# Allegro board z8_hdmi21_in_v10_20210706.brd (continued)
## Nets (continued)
GND: C1.2 C2.2 C3.2 C4.1 C5.2 C6.2 C7.2 C8.1 C9.2 C10.2 C11.2 C12.2 C13.1 C14.2 C15.2 C16.2 C17.2 C18.2 C19.2 C20.2 C21.2 C22.2 C23.2 C24.2 C25.2 C26.2 C27.2 C28.1 C29.2 C30.2 C31.2 C32.2 C33.2 C34.2 C36.2 C37.2 C38.2 C39.2 C40.2 C41.2 C42.2 C43.2 C44.1 C45.1 C46.1 C49.1 C50.2 C51.2 C52.2 C53.2 C54.2 C55.2 C56.2 C57.2 C58.2 C59.1 C60.2 C61.2 C62.2 C63.2 C64.2 C65.2 C66.2 C67.2 C68.2 C69.2 C70.2 C71.2 C72.2 C73.2 C75.2 C76.2 C77.2 C78.2 C79.2 C80.2 C81.2 C82.2 C83.2 C84.2 C85.2 C86.2 C87.2 C88.2 C89.2 C90.2 C91.2 C92.2 C93.2 C94.2 C95.2 C96.2 C97.2 C98.2 C99.2 C100.2 C101.2 C102.2 C103.2 C104.2 C105.2 C106.2 C107.2 C108.2 C109.2 C110.2 C111.1 C114.2 C118.2 C123.2 C124.2 C125.2 C126.2 C127.2 C128.2 C129.2 C131.2 C134.2 C135.2 C136.2 C137.2 C138.2 C139.2 C140.2 C141.2 C142.2 C143.2 C144.1 C145.2 C146.1 C147.2 C148.2 C149.2 C150.2 C151.2 C152.2 C153.2 C154.2 C155.2 C156.2 C157.2 C158.2 C159.2 C162.2 C163.2 C165.2 C166.2 C167.2 C168.2 C169.2 C170.2 C171.2 C173.2 C175.2 C176.2 C177.2 C179.2 C180.2 C182.1 C183.2 C188.2 C189.1 C192.2 C193.2 C195.2 C196.1 C197.2 C198.2 C200.2 C201.2 C203.2 C204.2 C205.2 C206.2 C207.2 C208.2 C209.2 C210.2 C211.2 C212.2 C213.2 C214.2 C215.2 C216.2 C217.2 C218.2 C219.2 C220.2 C221.2 C222.1 C223.2 C224.2 C225.2 C226.1 C227.2 C228.1 C229.2 C230.2 C231.2 C232.2 C233.2 C234.2 C235.2 C236.2 C237.2 C238.2 C239.2 C240.2 C241.2 C242.2 C243.2 C244.2 C248.2 C249.2 C253.2 C255.2 C256.2 C258.2 C265.2 C267.2 C268.2 C270.1 C271.1 C272.2 C273.2 C274.2 C275.2 C276.2 C277.2 C278.2 C279.2 C280.2 C281.1 C282.1 C283.2 C284.1 C285.1 C286.2 C287.2 C288.2 C289.2 C290.2 C291.2 C292.2 C293.2 C294.2 C297.2 C298.2 C299.2 C303.2 C304.2 C305.2 C306.2 C307.2 C308.2 C309.2 C310.2 C311.2 C312.2 C313.2 C314.2 C315.2 C316.2 C317.2 C318.2 C319.2 C320.2 C321.2 C322.2 C323.2 C324.2 C325.2 C326.2 C327.2 C328.2 C329.2 C330.2 C335.2 C337.2 C338.2 C339.2 C340.2 C341.2 C342.2 C343.2 C344.2 C345.2 C346.2 C347.2 C348.2 C349.2 C350.2 C351.2 C352.2 C353.2 C354.2 C355.2 C356.2 C357.2 C358.2 C359.2 C360.2 C361.2 C362.2 C363.2 C364.1 C365.2 C366.2 C367.2 C368.2 C369.2 C370.2 C371.2 C373.2 C374.2 C376.2 C377.2 C379.2 C380.2 C386.2 C387.2 C388.2 C389.2 C394.2 C395.2 C396.2 C397.2 C402.1 C403.1 C404.1 C405.1 C406.1 C407.1 C408.1 C409.1 C410.2 C411.1 C412.1 C413.1 C414.1 C415.1 C417.2 C421.2 C423.2 C425.2 C427.2 C429.2 C430.2 C432.2 C433.2 C434.2 C436.2 C437.2 C438.2 C439.2 C440.2 C441.2 C442.2 C443.2 C444.2 C445.2 C446.2 C447.2 C448.2 C449.2 C450.2 C451.2 C452.2 C453.2 C454.2 C455.2 C456.2 C457.2 C458.2 C459.2 C460.2 C461.2 C462.2 C463.2 C464.2 C465.2 C466.2 C467.2 C468.2 C469.2 C470.2 C471.2 C472.2 C473.2 C474.2 C475.2 C476.2 C477.2 C478.2 C479.2 C480.2 C481.2 C482.2 C483.2 C484.2 C485.2 C486.2 C487.2 C488.2 C489.2 C490.2 C491.2 C492.2 C493.2 C494.2 C495.2 C496.2 C497.2 C498.2 C499.2 C500.2 C501.2 C502.2 C503.2 C504.2 C505.2 C506.2 C507.2 C508.2 C509.2 C510.1 C511.1 C512.2 C513.2 C514.2 C515.2 C516.2 C517.2 C518.2 C519.2 C520.2 C521.2 C522.2 C523.2 C524.2 C525.2 C526.2 C527.2 C528.2 C529.2 C530.2 C531.2 C532.2 C533.2 C534.2 C535.2 C536.1 C537.1 C538.1 C539.1 C540.1 C541.1 C542.2 C543.2 C544.2 C545.2 C546.2 C547.2 C548.2 C549.2 C550.2 C551.2 C552.2 C553.2 C554.2 C555.2 C556.2 C557.2 C558.2 C559.2 C560.2 C561.2 C562.2 C563.2 C564.2 C565.2 C566.2 C567.2 C568.2 C569.2 C570.2 C571.2 C572.2 C573.2 C574.2 C575.2 C576.2 C577.2 C578.2 C579.2 C580.2 C581.2 C582.2 C583.2 C584.2 C585.2 C586.1 C587.1 C588.1 C589.1 C590.1 C591.2 C592.2 C593.2 C594.2 C595.2 C596.1 C597.1 C598.1 C599.1 C600.1 C601.1 C602.1 C603.1 C604.1 C605.1 C606.1 C607.1 C608.1 C609.2 C610.2 C611.2 C612.2 C613.2 C614.1 C615.1 C616.1 C617.1 C618.1 C619.1 C620.1 C621.1 C623.2 C624.2 C625.2 C627.1 C628.1 C629.1 C630.1 C631.1 C632.2 C700.2 C701.2 C702.2 C703.2 C704.1 FAN1.2 FAN2.2 HDMI1.2(DAT2_S) HDMI1.5(DAT1_S) HDMI1.8(DAT0_S) HDMI1.11(CLK_S) HDMI1.17(DDC/CEC GND) J4.2(6) J4.10 J6.2(DAT2_S) J6.5(DAT1_S) J6.8(DAT0_S) J6.11(CLK_S) J6.17(DDC/CEC GND) J8.2(DAT2_S) J8.5(DAT1_S) J8.8(DAT0_S) J8.11(CLK_S) J8.17(DDC/CEC GND) J10.2(DAT2_S) J10.5(DAT1_S) J10.8(DAT0_S) J10.11(CLK_S) J10.17(DDC/CEC GND) J11.6 J13.1 J13.2 J14.2(DAT2_S) J14.5(DAT1_S) J14.8(DAT0_S) J14.11(CLK_S) J14.17(DDC/CEC GND) J15.2 J15.3 JA1.3 JA1.4 JT1.AB1(G-CD1) JT1.AB2(G-CD2) JT1.AB3(G-CD3) JT1.AB4(G-CD4) JT1.AB5(G-CD5) JT1.AB6(G-CD6) JT1.AB7(G-CD7) JT1.AB8(G-CD8) JT1.AB9(G-CD9) JT1.AB10(G-CD10) JT1.CD1(G-CD5) JT1.CD2(G-CD4) JT1.CD3(G-CD3) JT1.CD4(G-CD2) JT1.CD5(G-CD1) JT1.CD6(G-CD6) JT1.CD7(G-CD7) JT1.CD8(G-CD8) JT1.CD9(G-CD9) JT1.CD10(G-CD10) L20.2 P1.A7(GND_A7) P1.A12(GND_A12) P1.A17(GND_A17) P1.A22(GND_A22) P1.A27(GND_A27) P1.A28(GND_A28) P1.A30(GND_A30) P1.A31(GND_A31) P1.A32(GND_A32) P1.A33(GND_A33) P1.AA2(GND_AA2) P1.AA12(GND_AA12) P1.AA17(GND_AA17) P1.AA22(GND_AA22) P1.AA25(GND_AA25) P1.AA26(GND_AA26) P1.AA29(GXBL1D_RX_CH2N,GXBL1D_REFCLK2N_) P1.AA30(GXBL1D_RX_CH2P,GXBL1D_REFCLK2P_) P1.AA31(GND_AA31) P1.AA32(GND_AA32) P1.AB4(GND_AB4) P1.AB19(GND_AB19) P1.AB26(GND_AB26) P1.AB29(GND_AB29) P1.AB30(GND_AB30) P1.AB31(GXBL1D_RX_CH1N,GXBL1D_REFCLK1N_) P1.AB32(GXBL1D_RX_CH1P,GXBL1D_REFCLK1P_) P1.AB33(GND_AB33) P1.AB34(GND_AB34) P1.AC1(GND_AC1) P1.AC11(GND_AC11) P1.AC16(GND_AC16) P1.AC17(IO_2A_0_AC17/DEV_CLRN/LVDS2A_24) P1.AC19(VREFB2AN0_2A_AC19) P1.AC25(GND_AC25) P1.AC29(GXBL1D_RX_CH0N,GXBL1D_REFCLK0N_) P1.AC30(GXBL1D_RX_CH0P,GXBL1D_REFCLK0P_) P1.AC31(GND_AC31) P1.AC32(GND_AC32) P1.AD3(GND_AD3) P1.AD13(GND_AD13) P1.AD18(GND_AD18) P1.AD21(GND_AD21) P1.AD23(GND_AD23) P1.AD26(GND_AD26) P1.AD29(GND_AD29) P1.AD30(GND_AD30) P1.AD31(GXBL1C_RX_CH5N,GXBL1C_REFCLK5N_) P1.AD32(GXBL1C_RX_CH5P,GXBL1C_REFCLK5P_) P1.AD33(GND_AD33) P1.AD34(GND_AD34) P1.AE5(GND_AE5) P1.AE13(GND_AE13) P1.AE15(GND_AE15) P1.AE26(GND_AE26) P1.AE29(GXBL1C_RX_CH4N,GXBL1C_REFCLK4N_) P1.AE30(GXBL1C_RX_CH4P,GXBL1C_REFCLK4P_) P1.AE31(GND_AE31) P1.AE32(GND_AE32) P1.AF2(GND_AF2) P1.AF7(GND_AF7) P1.AF18(IO_2A_2_AF18/DEV_OE/LVDS2A_23P/) P1.AF26(GND_AF26) P1.AF29(GND_AF29) P1.AF30(GND_AF30) P1.AF33(GND_AF33) P1.AF34(GND_AF34) P1.AG4(GND_AG4) P1.AG14(GND_AG14) P1.AG19(GND_AG19) P1.AG26(GND_AG26) P1.AG27(GND_AG27) P1.AG28(GND_AG28) P1.AG31(GND_AG31) P1.AG32(GND_AG32) P1.AH1(GND_AH1) P1.AH6(GND_AH6) P1.AH11(GND_AH11) P1.AH21(GND_AH21) P1.AH28(GND_AH28) P1.AH29(GND_AH29) P1.AH30(GND_AH30) P1.AH33(GND_AH33) P1.AH34(GND_AH34) P1.AJ3(GND_AJ3) P1.AJ8(GND_AJ8) P1.AJ13(GND_AJ13) P1.AJ16(IO_2A_12_AJ16/PR_REQUEST/LVDS2A) P1.AJ18(GND_AJ18) P1.AJ28(GND_AJ28) P1.AJ31(GND_AJ31) P1.AJ32(GND_AJ32) P1.AK5(GND_AK5) P1.AK10(GND_AK10) P1.AK25(GND_AK25) P1.AK28(GND_AK28) P1.AK29(GND_AK29) P1.AK30(GND_AK30) P1.AK33(GND_AK33) P1.AK34(GND_AK34) P1.AL2(GND_AL2) P1.AL7(GND_AL7) P1.AL12(GND_AL12) P1.AL17(GND_AL17) P1.AL22(GND_AL22) P1.AL28(GND_AL28) P1.AL31(GND_AL31) P1.AL32(GND_AL32) P1.AM4(GND_AM4) P1.AM9(GND_AM9) P1.AM14(GND_AM14) P1.AM19(GND_AM19) P1.AM24(GND_AM24) P1.AM28(GND_AM28) P1.AM29(GND_AM29) P1.AM30(GND_AM30) P1.AM33(GND_AM33) P1.AM34(GND_AM34) P1.AN6(GND_AN6) P1.AN11(GND_AN11) P1.AN16(GND_AN16) P1.AN21(GND_AN21) P1.AN26(GND_AN26) P1.AN30(GND_AN30) P1.AN31(GND_AN31) P1.AN32(GND_AN32) P1.AP8(GND_AP8) P1.AP11(GND_AP11) P1.AP13(GND_AP13) P1.AP18(GND_AP18) P1.AP23(GND_AP23) P1.AP28(GND_AP28) P1.AP30(GND_AP30) P1.AP33(GND_AP33) P1.B2(GND_B2) P1.B4(GND_B4) P1.B9(GND_B9) P1.B14(GND_B14) P1.B19(GND_B19) P1.B24(GND_B24) P1.B28(GND_B28) P1.B29(GND_B29) P1.B30(GND_B30) P1.B33(GND_B33) P1.B34(GND_B34) P1.C1(GND_C1) P1.C6(GND_C6) P1.C11(GND_C11) P1.C14(TEMPDIODEN_C14) P1.C16(GND_C16) P1.C21(GND_C21) P1.C26(GND_C26) P1.C28(GND_C28) P1.C29(GXBL1F_RX_CH5N,GXBL1F_REFCLK5N_) P1.C30(GXBL1F_RX_CH5P,GXBL1F_REFCLK5P_) P1.C31(GND_C31) P1.C32(GND_C32) P1.D3(GND_D3) P1.D8(GND_D8) P1.D13(GND_D13) P1.D14(TEMPDIODEP_D14) P1.D18(GND_D18) P1.D23(GND_D23) P1.D28(GND_D28) P1.D29(GND_D29) P1.D30(GND_D30) P1.D33(GND_D33) P1.D34(GND_D34) P1.E5(GND_E5) P1.E10(GND_E10) P1.E14(VSIGP_0_E14) P1.E15(GND_E15) P1.E20(GND_E20) P1.E25(GND_E25) P1.E28(GND_E28) P1.E29(GXBL1F_RX_CH4N,GXBL1F_REFCLK4N_) P1.E30(GXBL1F_RX_CH4P,GXBL1F_REFCLK4P_) P1.E31(GND_E31) P1.E32(GND_E32) P1.F2(GND_F2) P1.F7(GND_F7) P1.F14(VSIGN_0_F14) P1.F27(GND_F27) P1.F28(GND_F28) P1.F29(GND_F29) P1.F30(GND_F30) P1.F33(GND_F33) P1.F34(GND_F34) P1.G4(GND_G4) P1.G9(GND_G9) P1.G14(GND_G14) P1.G28(GND_G28) P1.G29(GXBL1F_RX_CH3N,GXBL1F_REFCLK3N_) P1.G30(GXBL1F_RX_CH3P,GXBL1F_REFCLK3P_) P1.G31(GND_G31) P1.G32(GND_G32) P1.H1(GND_H1) P1.H6(GND_H6) P1.H14(VSIGP_1_H14) P1.H16(GND_H16) P1.H21(GND_H21) P1.H26(GND_H26) P1.H28(GND_H28) P1.H29(GND_H29) P1.H30(GND_H30) P1.H33(GND_H33) P1.H34(GND_H34) P1.J3(GND_J3) P1.J8(GND_J8) P1.J14(VSIGN_1_J14) P1.J15(GND_J15) P1.J16(GND_J16) P1.J28(GND_J28) P1.J29(GXBL1F_RX_CH2N,GXBL1F_REFCLK2N_) P1.J30(GXBL1F_RX_CH2P,GXBL1F_REFCLK2P_) P1.J31(GND_J31) P1.J32(GND_J32) P1.K5(GND_K5) P1.K15(GND_K15) P1.K16(GND_K16) P1.K17(VREFB2LN0_2L_K17) P1.K20(GND_K20) P1.K26(GND_K26) P1.K27(GND_K27) P1.K28(GND_K28) P1.K29(GND_K29) P1.K30(GND_K30) P1.K31(GXBL1F_RX_CH1N,GXBL1F_REFCLK1N_) P1.K32(GXBL1F_RX_CH1P,GXBL1F_REFCLK1P_) P1.K33(GND_K33) P1.K34(GND_K34) P1.L2(GND_L2) P1.L7(GND_L7) P1.L12(GND_L12) P1.L15(GND_L15) P1.L16(GND_L16) P1.L17(GND_L17) P1.L22(GND_L22) P1.L25(GND_L25) P1.L29(GXBL1F_RX_CH0N,GXBL1F_REFCLK0N_) P1.L30(GXBL1F_RX_CH0P,GXBL1F_REFCLK0P_) P1.L31(GND_L31) P1.L32(GND_L32) P1.M4(GND_M4) P1.M14(GND_M14) P1.M15(GND_M15) P1.M16(GND_M16) P1.M19(GND_M19) P1.M25(GND_M25) P1.M26(GND_M26) P1.M29(GND_M29) P1.M30(GND_M30) P1.M31(GXBL1E_RX_CH5N,GXBL1E_REFCLK5N_) P1.M32(GXBL1E_RX_CH5P,GXBL1E_REFCLK5P_) P1.M33(GND_M33) P1.M34(GND_M34) P1.N1(GND_N1) P1.N6(GND_N6) P1.N21(GND_N21) P1.N26(GND_N26) P1.N29(GXBL1E_RX_CH4N,GXBL1E_REFCLK4N_) P1.N30(GXBL1E_RX_CH4P,GXBL1E_REFCLK4P_) P1.N31(GND_N31) P1.N32(GND_N32) P1.P3(GND_P3) P1.P13(GND_P13) P1.P18(GND_P18) P1.P23(GND_P23) P1.P26(GND_P26) P1.P29(GND_P29) P1.P30(GND_P30) P1.P31(GXBL1E_RX_CH3N,GXBL1E_REFCLK3N_) P1.P32(GXBL1E_RX_CH3P,GXBL1E_REFCLK3P_) P1.P33(GND_P33) P1.P34(GND_P34) P1.R5(GND_R5) P1.R10(GND_R10) P1.R15(GND_R15) P1.R20(GND_R20) P1.R25(GND_R25) P1.R29(GXBL1E_RX_CH2N,GXBL1E_REFCLK2N_) P1.R30(GXBL1E_RX_CH2P,GXBL1E_REFCLK2P_) P1.R31(GND_R31) P1.R32(GND_R32) P1.T2(GND_T2) P1.T12(GND_T12) P1.T17(GND_T17) P1.T22(GND_T22) P1.T26(GND_T26) P1.T29(GND_T29) P1.T30(GND_T30) P1.T31(GXBL1E_RX_CH1N,GXBL1E_REFCLK1N_) P1.T32(GXBL1E_RX_CH1P,GXBL1E_REFCLK1P_) P1.T33(GND_T33) P1.T34(GND_T34) P1.U4(GND_U4) P1.U14(GND_U14) P1.U19(GND_U19) P1.U24(GND_U24) P1.U26(GND_U26) P1.U29(GXBL1E_RX_CH0N,GXBL1E_REFCLK0N_) P1.U30(GXBL1E_RX_CH0P,GXBL1E_REFCLK0P_) P1.U31(GND_U31) P1.U32(GND_U32) P1.V1(GND_V1) P1.V6(GND_V6) P1.V11(GND_V11) P1.V16(GND_V16) P1.V21(GND_V21) P1.V25(GND_V25) P1.V26(GND_V26) P1.V29(GND_V29) P1.V30(GND_V30) P1.V31(GXBL1D_RX_CH5N,GXBL1D_REFCLK5N_) P1.V32(GXBL1D_RX_CH5P,GXBL1D_REFCLK5P_) P1.V33(GND_V33) P1.V34(GND_V34) P1.W3(GND_W3) P1.W13(GND_W13) P1.W18(GND_W18) P1.W23(GND_W23) P1.W25(GND_W25) P1.W29(GXBL1D_RX_CH4N,GXBL1D_REFCLK4N_) P1.W30(GXBL1D_RX_CH4P,GXBL1D_REFCLK4P_) P1.W31(GND_W31) P1.W32(GND_W32) P1.Y10(GND_Y10) P1.Y15(GND_Y15) P1.Y20(GND_Y20) P1.Y25(GND_Y25) P1.Y26(GND_Y26) P1.Y29(GND_Y29) P1.Y30(GND_Y30) P1.Y31(GXBL1D_RX_CH3N,GXBL1D_REFCLK3N_) P1.Y32(GXBL1D_RX_CH3P,GXBL1D_REFCLK3P_) P1.Y33(GND_Y33) P1.Y34(GND_Y34) Q1.2(S) Q2.2(S) Q3.2(S) Q4.2(S) Q5.2(S) Q6.2(S) R3.1 R4.1 R5.1 R9.2 R10.1 R14.1 R23.1 R26.1 R27.1 R28.1 R29.1 R40.2 R44.1 R48.1 R49.1 R50.1 R52.1 R56.2 R58.1 R59.1 R60.1 R65.1 R67.2 R68.2 R70.2 R76.2 R78.1 R89.1 R90.2 R91.2 R95.2 R114.2 R116.1 R117.1 R121.1 R122.1 R124.2 R125.2 R127.2 R134.1 R135.1 R138.1 R147.1 R159.2 R160.2 R163.2 R168.1 R176.2 R178.2 R193.1 R194.1 R199.1 R201.2 R202.2 R204.2 R211.1 R212.1 R221.1 R226.2 R227.2 R228.1 R232.2 R237.2 R238.1 R245.1 R247.1 R251.2 R253.1 R254.2 R257.1 R259.2 R261.1 R263.2 R264.2 R266.2 R274.1 R284.2 R286.2 R287.2 R290.2 R291.1 R293.1 R308.1 R309.1 R310.1 R311.1 R312.1 R313.1 R314.1 R315.1 R328.1 R329.1 R330.1 R336.2 R339.2 R340.2 R342.2 R345.2 R346.2 R348.2 R351.2 R352.2 R369.2 R370.2 R372.2 R382.2 R383.2 R389.2 R392.2 R396.1 R403.2 R409.1 R412.2 R414.2 R417.1 R418.2 R421.2 R427.1 R429.1 R434.1 R439.2 R440.2 R443.1 R450.2 R453.2 R454.2 R457.2 R460.2 R461.1 R463.2 R464.2 R470.2 R472.2 R476.2 R477.2 R484.2 R486.2 R490.2 R491.2 R492.2 U1.4(T-) U2.1(GND) U3.3(GND1) U3.8(GND2) U4.3(GND1) U4.8(GND2) U5.4(PGND) U5.8(GND) U5.11(TPAD) U6.B3(VSS) U7.3(GND1) U7.8(GND2) U8.A2(DQ13) U8.A3(DQ15) U8.A7(DQ12) U8.A9(VSS0) U8.B1(VSSQ0) U8.B3(VSS1) U8.B8(DQ14) U8.B9(VSSQ1) U8.C2(DQ11) U8.C3(DQ9) U8.C8(DQ10) U8.D1(VSSQ2) U8.D7(DQ8) U8.D8(VSSQ3) U8.E1(VSS2) U8.E2(VSSQ4) U8.E8(VSSQ5) U8.F9(VSSQ6) U8.G1(VSSQ7) U8.G8(VSS3) U8.G9(VSSQ8) U8.J2(VSS4) U8.J8(VSS5) U8.M1(VSS6) U8.M9(VSS7) U8.P1(VSS8) U8.P9(VSS9) U8.T1(VSS10) U8.T3(A13) U8.T7(A14) U8.T9(VSS11) U9.3(PGND1) U9.4(PGND2) U9.5(PGND3) U9.8(PGND4) U9.9(PGND5) U9.10(PGND6) U9.12(AGND) U10.A2(DQ13) U10.A3(DQ15) U10.A7(DQ12) U10.A9(VSS0) U10.B1(VSSQ0) U10.B3(VSS1) U10.B8(DQ14) U10.B9(VSSQ1) U10.C2(DQ11) U10.C3(DQ9) U10.C8(DQ10) U10.D1(VSSQ2) U10.D7(DQ8) U10.D8(VSSQ3) U10.E1(VSS2) U10.E2(VSSQ4) U10.E8(VSSQ5) U10.F9(VSSQ6) U10.G1(VSSQ7) U10.G8(VSS3) U10.G9(VSSQ8) U10.J2(VSS4) U10.J8(VSS5) U10.M1(VSS6) U10.M9(VSS7) U10.P1(VSS8) U10.P9(VSS9) U10.T1(VSS10) U10.T3(A13) U10.T7(A14) U10.T9(VSS11) U11.A9(VSS0) U11.B1(VSSQ0) U11.B3(VSS1) U11.B9(VSSQ1) U11.D1(VSSQ2) U11.D8(VSSQ3) U11.E1(VSS2) U11.E2(VSSQ4) U11.E8(VSSQ5) U11.F9(VSSQ6) U11.G1(VSSQ7) U11.G8(VSS3) U11.G9(VSSQ8) U11.J2(VSS4) U11.J8(VSS5) U11.M1(VSS6) U11.M9(VSS7) U11.P1(VSS8) U11.P9(VSS9) U11.T1(VSS10) U11.T3(A13) U11.T7(A14) U11.T9(VSS11) U12.A9(VSS0) U12.B1(VSSQ0) U12.B3(VSS1) U12.B9(VSSQ1) U12.D1(VSSQ2) U12.D8(VSSQ3) U12.E1(VSS2) U12.E2(VSSQ4) U12.E8(VSSQ5) U12.F9(VSSQ6) U12.G1(VSSQ7) U12.G8(VSS3) U12.G9(VSSQ8) U12.J2(VSS4) U12.J8(VSS5) U12.M1(VSS6) U12.M9(VSS7) U12.P1(VSS8) U12.P9(VSS9) U12.T1(VSS10) U12.T3(A13) U12.T7(A14) U12.T9(VSS11) U13.2(GND) U14.4(PGND) U14.8(GND) U14.11(TPAD) U15.3(GND1) U15.8(GND2) U16.A9(VSS0) U16.B1(VSSQ0) U16.B3(VSS1) U16.B9(VSSQ1) U16.D1(VSSQ2) U16.D8(VSSQ3) U16.E1(VSS2) U16.E2(VSSQ4) U16.E8(VSSQ5) U16.F9(VSSQ6) U16.G1(VSSQ7) U16.G8(VSS3) U16.G9(VSSQ8) U16.J2(VSS4) U16.J8(VSS5) U16.M1(VSS6) U16.M9(VSS7) U16.P1(VSS8) U16.P9(VSS9) U16.T1(VSS10) U16.T3(A13) U16.T7(A14) U16.T9(VSS11) U17.3(GND1) U17.8(GND2) U19.7(GND1) U19.19(GND2) U19.30(GND3) U19.41(GND4) U19.49(PAD) U20.3(GND1) U20.8(GND2) U21.1(GND) U22.A9(VSS0) U22.B1(VSSQ0) U22.B3(VSS1) U22.B9(VSSQ1) U22.D1(VSSQ2) U22.D8(VSSQ3) U22.E1(VSS2) U22.E2(VSSQ4) U22.E8(VSSQ5) U22.F9(VSSQ6) U22.G1(VSSQ7) U22.G8(VSS3) U22.G9(VSSQ8) U22.J2(VSS4) U22.J8(VSS5) U22.M1(VSS6) U22.M9(VSS7) U22.P1(VSS8) U22.P9(VSS9) U22.T1(VSS10) U22.T3(A13) U22.T7(A14) U22.T9(VSS11) U23.2(GND) U24.3(GND1) U24.8(GND2) U25.3(PGND1) U25.4(PGND2) U25.5(PGND3) U25.8(PGND4) U25.9(PGND5) U25.10(PGND6) U25.12(AGND) U26.4(I2C_LSB) U26.6(FDBK_N) U26.23(RSVD_GND) U26.25(EPAD) U27.3(GND1) U27.8(GND2) U28.A9(VSS0) U28.B1(VSSQ0) U28.B3(VSS1) U28.B9(VSSQ1) U28.D1(VSSQ2) U28.D8(VSSQ3) U28.E1(VSS2) U28.E2(VSSQ4) U28.E8(VSSQ5) U28.F9(VSSQ6) U28.G1(VSSQ7) U28.G8(VSS3) U28.G9(VSSQ8) U28.J2(VSS4) U28.J8(VSS5) U28.M1(VSS6) U28.M9(VSS7) U28.P1(VSS8) U28.P9(VSS9) U28.T1(VSS10) U28.T3(A13) U28.T7(A14) U28.T9(VSS11) U29.7(GND1) U29.19(GND2) U29.30(GND3) U29.41(GND4) U29.49(PAD) U30.3(GND1) U30.8(GND2) U31.1(GND) U32.A9(VSS0) U32.B1(VSSQ0) U32.B3(VSS1) U32.B9(VSSQ1) U32.D1(VSSQ2) U32.D8(VSSQ3) U32.E1(VSS2) U32.E2(VSSQ4) U32.E8(VSSQ5) U32.F9(VSSQ6) U32.G1(VSSQ7) U32.G8(VSS3) U32.G9(VSSQ8) U32.J2(VSS4) U32.J8(VSS5) U32.M1(VSS6) U32.M9(VSS7) U32.P1(VSS8) U32.P9(VSS9) U32.T1(VSS10) U32.T3(A13) U32.T7(A14) U32.T9(VSS11) U33.2(GND) U34.4(PGND) U34.8(GND) U34.11(TPAD) U35.3(GND1) U35.8(GND2) U36.3(GND1) U36.8(GND2) U37.7(GND1) U37.19(GND2) U37.30(GND3) U37.41(GND4) U37.49(PAD) U38.4(GND) U39.4(I2C_LSB) U39.6(FDBK_N) U39.23(RSVD_GND) U39.25(EPAD) U40.A2(DQ13) U40.A3(DQ15) U40.A7(DQ12) U40.A9(VSS0) U40.B1(VSSQ0) U40.B3(VSS1) U40.B8(DQ14) U40.B9(VSSQ1) U40.C2(DQ11) U40.C3(DQ9) U40.C8(DQ10) U40.D1(VSSQ2) U40.D7(DQ8) U40.D8(VSSQ3) U40.E1(VSS2) U40.E2(VSSQ4) U40.E8(VSSQ5) U40.F9(VSSQ6) U40.G1(VSSQ7) U40.G8(VSS3) U40.G9(VSSQ8) U40.J2(VSS4) U40.J8(VSS5) U40.M1(VSS6) U40.M9(VSS7) U40.P1(VSS8) U40.P9(VSS9) U40.T1(VSS10) U40.T3(A13) U40.T7(A14) U40.T9(VSS11) U41.3(GND1) U41.8(GND2) U42.1(GND) U43.8(VSSA) U43.23(VSS) U43.47(VSSS) U44.2(GND) U45.2(GND) U46.3(GND1) U46.8(GND2) U47.3(GND1) U47.8(GND2) U48.7(GND1) U48.19(GND2) U48.30(GND3) U48.41(GND4) U48.49(PAD) U49.3(GND1) U49.8(GND2) U50.2(GND) U51.3(PGND1) U51.4(PGND2) U51.5(PGND3) U51.8(PGND4) U51.9(PGND5) U51.10(PGND6) U51.12(AGND) U52.3(PGND1) U52.4(PGND2) U52.5(PGND3) U52.8(PGND4) U52.9(PGND5) U52.10(PGND6) U52.12(AGND) U53.3(PGND1) U53.4(PGND2) U53.5(PGND3) U53.8(PGND4) U53.9(PGND5) U53.10(PGND6) U53.12(AGND) U54.3(PGND1) U54.4(PGND2) U54.5(PGND3) U54.8(PGND4) U54.9(PGND5) U54.10(PGND6) U54.12(AGND) U55.1(GND) U56.23(PWPD) U59.25(VDD_SEL) U59.52(RESET) U59.55(GND) Y1.2(GND) Y2.2(GND#2) Y2.4(GND#4) Y3.2(GND) Y4.2(GND#2) Y4.4(GND#4) Y5.2(GND#2) Y5.4(GND#4)
VCC_D0V9: C305.1 C306.1 C308.1 C309.1 C310.1 C311.1 C444.1 C446.1 C452.1 C453.1 C454.1 C455.1 C456.1 C457.1 C460.1 C461.1 C462.1 C463.1 C466.1 C469.1 C471.1 C474.1 C475.1 C478.1 C479.1 C480.1 C481.1 C482.1 C483.1 C486.1 C488.1 C489.1 C491.1 C494.1 C495.1 C496.1 C497.1 C498.1 C499.1 C500.1 C501.1 C502.1 C503.1 C504.1 C505.1 C506.1 C507.1 C508.1 C509.1 C514.1 C515.1 C516.1 C517.1 C518.1 C519.1 C520.1 C522.1 C523.1 C524.1 C525.1 C526.1 C527.1 C528.1 C529.1 C533.1 C542.1 C543.1 C544.1 C545.1 C546.1 C549.1 C550.1 C551.1 C552.1 C554.1 C556.1 C557.1 C560.1 C562.1 C563.1 C564.1 C565.1 C566.1 C567.1 C568.1 C569.1 C570.1 C571.1 C574.1 C575.1 C577.1 C578.1 C622.1 C623.1 C624.1 C625.1 L11.1 P1.AA11(VCC_AA11) P1.AA13(VCC_AA13) P1.AA16(VCC_AA16) P1.AA18(VCC_AA18) P1.AA19(VCC_AA19) P1.AA23(VCC_AA23) P1.AA24(VCC_AA24) P1.AB12(VCC_AB12) P1.AB13(VCC_AB13) P1.AB14(VCC_AB14) P1.AB15(VCCP_AB15) P1.AB16(VCCP_AB16) P1.AB17(VCC_AB17) P1.AB18(VCC_AB18) P1.AB20(VCCP_AB20) P1.AB21(VCC_AB21) P1.AB22(VCCP_AB22) P1.AB23(VCC_AB23) P1.AB24(VCC_AB24) P1.AB25(VCC_AB25) P1.AC18(VCC_AC18) P1.AC21(VCC_AC21) P1.N12(VCC_N12) P1.N13(VCC_N13) P1.N14(VCCP_N14) P1.N15(VCCP_N15) P1.N16(VCC_N16) P1.N17(VCC_N17) P1.N18(VCC_N18) P1.N19(VCCP_N19) P1.N20(VCCP_N20) P1.N22(VCCP_N22) P1.N23(VCC_N23) P1.N24(VCC_N24) P1.N25(VCC_N25) P1.P11(VCC_P11) P1.P12(VCC_P12) P1.P14(VCC_P14) P1.P17(VCC_P17) P1.P22(VCC_P22) P1.P24(VCC_P24) P1.P25(VCC_P25) P1.R11(VCC_R11) P1.R12(VCC_R12) P1.R13(VCC_R13) P1.R14(VCC_R14) P1.R16(VCC_R16) P1.R17(VCC_R17) P1.R18(VCC_R18) P1.R19(VCC_R19) P1.R21(VCC_R21) P1.R22(VCC_R22) P1.R23(VCC_R23) P1.R24(VCC_R24) P1.T11(VCC_T11) P1.T13(VCC_T13) P1.T19(VCC_T19) P1.T20(VCC_T20) P1.T21(VCC_T21) P1.T23(VCC_T23) P1.T24(VCC_T24) P1.T25(VCC_T25) P1.U11(VCC_U11) P1.U12(VCC_U12) P1.U13(VCCERAM_U13) P1.U15(VCC_U15) P1.U16(VCC_U16) P1.U17(VCCERAM_U17) P1.U18(VCCERAM_U18) P1.U20(VCC_U20) P1.U21(VCC_U21) P1.U22(VCCERAM_U22) P1.U23(VCCERAM_U23) P1.U25(VCC_U25) P1.V12(VCC_V12) P1.V13(VCC_V13) P1.V14(VCC_V14) P1.V15(VCC_V15) P1.V17(VCC_V17) P1.V18(VCC_V18) P1.V19(VCC_V19) P1.V20(VCC_V20) P1.V22(VCC_V22) P1.V23(VCC_V23) P1.V24(VCC_V24) P1.W11(VCC_W11) P1.W12(VCC_W12) P1.W14(VCC_W14) P1.W15(VCC_W15) P1.W16(VCC_W16) P1.W17(VCC_W17) P1.W19(VCC_W19) P1.W20(VCC_W20) P1.W21(VCC_W21) P1.W22(VCC_W22) P1.W24(VCC_W24) P1.Y11(VCC_Y11) P1.Y12(VCC_Y12) P1.Y13(VCC_Y13) P1.Y14(VCC_Y14) P1.Y16(VCC_Y16) P1.Y19(VCC_Y19) P1.Y21(VCC_Y21) P1.Y22(VCC_Y22) P1.Y23(VCC_Y23) P1.Y24(VCC_Y24) R283.2 R422.2 R425.1
VCC_D1V8: C458.1 C476.1 C521.1 C553.1 C558.1 C581.1 C700.1 C701.1 C702.1 C703.1 L34.2 L35.2 P1.AC26(VCCH_GXBL_AC26) P1.L26(VCCH_GXBL_L26) P1.R26(VCCH_GXBL_R26) P1.T16(VCCA_PLL_T16) P1.T18(VCCA_PLL_T18) P1.W26(VCCH_GXBL_W26)
VCC_DDR3: C7.1 C14.1 C15.1 C16.1 C17.1 C18.1 C19.1 C23.1 C24.1 C30.1 C31.1 C34.1 C37.1 C38.1 C39.1 C40.1 C41.1 C42.1 C50.1 C51.1 C52.1 C53.1 C54.1 C55.1 C61.1 C62.1 C63.1 C69.1 C70.1 C71.1 C72.1 C73.1 C74.1 C75.1 C77.1 C78.1 C79.1 C81.1 C82.1 C83.1 C84.1 C85.1 C86.1 C87.1 C88.1 C90.1 C91.1 C92.1 C93.1 C94.1 C96.1 C97.1 C98.1 C99.1 C100.1 C101.1 C102.1 C103.1 C104.1 C105.1 C107.1 C108.1 C109.1 C110.1 C114.1 C118.1 C125.1 C126.1 C127.1 C128.1 C129.1 C134.1 C135.1 C136.1 C137.1 C138.1 C139.1 C142.1 C150.1 C151.1 C152.1 C153.1 C154.1 C165.1 C166.1 C167.1 C168.1 C169.1 C170.1 C175.1 C206.1 C207.1 C208.1 C209.1 C210.1 C215.1 C216.1 C217.1 C218.1 C219.1 C220.1 C223.1 C224.1 C225.1 C232.1 C233.1 C234.1 C235.1 C236.1 C238.1 C239.1 C240.1 C241.1 C242.1 C243.1 C255.1 C275.1 C276.1 C277.1 C278.1 C279.1 C423.1 C430.1 C433.1 C436.1 C437.1 C438.1 C439.1 C441.1 C442.1 C451.1 C468.1 C493.1 C532.1 C534.1 C576.1 C584.1 C591.1 C592.1 L2.2 P1.AA7(VCCIO3C_AA7) P1.AB9(VCCIO3B_AB9) P1.AC6(VCCIO3B_AC6) P1.AD8(VCCIO3B_AD8) P1.AE10(VCCIO3A_AE10) P1.AE25(VCCIO2J_AE25) P1.AF12(VCCIO3A_AF12) P1.AG9(VCCIO3A_AG9) P1.AG24(VCCIO2J_AG24) P1.AJ23(VCCIO2J_AJ23) P1.F22(VCCIO2K_F22) P1.G24(VCCIO2K_G24) P1.J23(VCCIO2K_J23) P1.P8(VCCIO3D_P8) P1.T7(VCCIO3D_T7) P1.U9(VCCIO3D_U9) P1.W8(VCCIO3C_W8) P1.Y5(VCCIO3C_Y5) R38.1 R55.2 R64.1 R195.1 U5.2(VLDOIN) U8.A1(VDDQ0) U8.A8(VDDQ1) U8.B2(VDD0) U8.C1(VDDQ2) U8.C9(VDDQ3) U8.D2(VDDQ4) U8.D9(VDD1) U8.E9(VDDQ5) U8.F1(VDDQ6) U8.G7(VDD2) U8.H2(VDDQ7) U8.H9(VDDQ8) U8.K2(VDD3) U8.K8(VDD4) U8.N1(VDD5) U8.N9(VDD6) U8.R1(VDD7) U8.R9(VDD8) U10.A1(VDDQ0) U10.A8(VDDQ1) U10.B2(VDD0) U10.C1(VDDQ2) U10.C9(VDDQ3) U10.D2(VDDQ4) U10.D9(VDD1) U10.E9(VDDQ5) U10.F1(VDDQ6) U10.G7(VDD2) U10.H2(VDDQ7) U10.H9(VDDQ8) U10.K2(VDD3) U10.K8(VDD4) U10.N1(VDD5) U10.N9(VDD6) U10.R1(VDD7) U10.R9(VDD8) U11.A1(VDDQ0) U11.A8(VDDQ1) U11.B2(VDD0) U11.C1(VDDQ2) U11.C9(VDDQ3) U11.D2(VDDQ4) U11.D9(VDD1) U11.E9(VDDQ5) U11.F1(VDDQ6) U11.G7(VDD2) U11.H2(VDDQ7) U11.H9(VDDQ8) U11.K2(VDD3) U11.K8(VDD4) U11.N1(VDD5) U11.N9(VDD6) U11.R1(VDD7) U11.R9(VDD8) U12.A1(VDDQ0) U12.A8(VDDQ1) U12.B2(VDD0) U12.C1(VDDQ2) U12.C9(VDDQ3) U12.D2(VDDQ4) U12.D9(VDD1) U12.E9(VDDQ5) U12.F1(VDDQ6) U12.G7(VDD2) U12.H2(VDDQ7) U12.H9(VDDQ8) U12.K2(VDD3) U12.K8(VDD4) U12.N1(VDD5) U12.N9(VDD6) U12.R1(VDD7) U12.R9(VDD8) U14.2(VLDOIN) U16.A1(VDDQ0) U16.A8(VDDQ1) U16.B2(VDD0) U16.C1(VDDQ2) U16.C9(VDDQ3) U16.D2(VDDQ4) U16.D9(VDD1) U16.E9(VDDQ5) U16.F1(VDDQ6) U16.G7(VDD2) U16.H2(VDDQ7) U16.H9(VDDQ8) U16.K2(VDD3) U16.K8(VDD4) U16.N1(VDD5) U16.N9(VDD6) U16.R1(VDD7) U16.R9(VDD8) U22.A1(VDDQ0) U22.A8(VDDQ1) U22.B2(VDD0) U22.C1(VDDQ2) U22.C9(VDDQ3) U22.D2(VDDQ4) U22.D9(VDD1) U22.E9(VDDQ5) U22.F1(VDDQ6) U22.G7(VDD2) U22.H2(VDDQ7) U22.H9(VDDQ8) U22.K2(VDD3) U22.K8(VDD4) U22.N1(VDD5) U22.N9(VDD6) U22.R1(VDD7) U22.R9(VDD8) U28.A1(VDDQ0) U28.A8(VDDQ1) U28.B2(VDD0) U28.C1(VDDQ2) U28.C9(VDDQ3) U28.D2(VDDQ4) U28.D9(VDD1) U28.E9(VDDQ5) U28.F1(VDDQ6) U28.G7(VDD2) U28.H2(VDDQ7) U28.H9(VDDQ8) U28.K2(VDD3) U28.K8(VDD4) U28.N1(VDD5) U28.N9(VDD6) U28.R1(VDD7) U28.R9(VDD8) U32.A1(VDDQ0) U32.A8(VDDQ1) U32.B2(VDD0) U32.C1(VDDQ2) U32.C9(VDDQ3) U32.D2(VDDQ4) U32.D9(VDD1) U32.E9(VDDQ5) U32.F1(VDDQ6) U32.G7(VDD2) U32.H2(VDDQ7) U32.H9(VDDQ8) U32.K2(VDD3) U32.K8(VDD4) U32.N1(VDD5) U32.N9(VDD6) U32.R1(VDD7) U32.R9(VDD8) U34.2(VLDOIN) U40.A1(VDDQ0) U40.A8(VDDQ1) U40.B2(VDD0) U40.C1(VDDQ2) U40.C9(VDDQ3) U40.D2(VDDQ4) U40.D9(VDD1) U40.E9(VDDQ5) U40.F1(VDDQ6) U40.G7(VDD2) U40.H2(VDDQ7) U40.H9(VDDQ8) U40.K2(VDD3) U40.K8(VDD4) U40.N1(VDD5) U40.N9(VDD6) U40.R1(VDD7) U40.R9(VDD8)
VCC_IO3V0: R7.1 R11.1 R77.1 R96.1 R105.1 R137.1 R164.1 R172.1 R210.1 R233.1 R242.1 R273.1 R292.1 R300.1 U2.2(VREF1) U21.2(VREF1) U31.2(VREF1) U42.2(VREF1) U55.2(VREF1)
VCCIO_D1V8: C307.1 C326.1 C327.1 C328.1 C329.1 C330.1 C385.1 C421.1 C425.1 C429.1 C440.1 C443.1 C450.1 C465.1 C473.1 C484.1 C485.1 C547.1 C548.1 C555.1 C572.1 C573.1 J4.4(7) L15.2 L34.1 L35.1 P1.AA14(VCCPT_AA14) P1.AA15(VCCPT_AA15) P1.AA20(VCCPT_AA20) P1.AA21(VCCPT_AA21) P1.AD14(VCCBAT_AD14) P1.AD15(VCCPGM_AD15) P1.AD16(VCCPGM_AD16) P1.AF17(VCCIO2A_AF17) P1.AH16(VCCIO2A_AH16) P1.AK15(VCCIO2A_AK15) P1.P15(VCCPT_P15) P1.P16(VCCPT_P16) P1.P19(VCCPT_P19) P1.P20(VCCPT_P20) P1.P21(VCCPT_P21) R15.1 R41.2 R43.1 R307.2 R398.2 R400.2 R401.2 R406.1 R408.1 R410.2 R413.2 R416.1 R420.2 U6.B4(VCC)
VCCIO_D3V0: C297.1 C298.1 C299.1 C585.1 C594.1 C595.1 L10.2 P1.F17(VCCIO2L_F17) P1.G19(VCCIO2L_G19) P1.J18(VCCIO2L_J18) R2.1 R285.2 R316.1 R325.1 R326.1 R327.1
VCCIO_EN: R237.1 U9.15(EN) U43.30(PA9) U50.1(EN/PG)
VCCR_D1V0: C304.1 C322.1 C323.1 C324.1 C325.1 C384.1 C432.1 C434.1 C467.1 C470.1 C512.1 C513.1 C559.1 C561.1 L8.1 L9.1 L14.2 P1.AA27(VCCR_GXBL1D_AA27) P1.AA28(VCCR_GXBL1D_AA28) P1.AE27(VCCR_GXBL1C_AE27) P1.AE28(VCCR_GXBL1C_AE28) P1.N27(VCCR_GXBL1F_N27) P1.N28(VCCR_GXBL1F_N28) P1.U27(VCCR_GXBL1E_U27) P1.U28(VCCR_GXBL1E_U28) R306.2
VCCT_D1V0: C290.1 C291.1 C292.1 C293.1 C447.1 C449.1 C477.1 C490.1 C530.1 C535.1 C582.1 C583.1 L8.2 L9.2 P1.AC27(VCCT_GXBL1C_AC27) P1.AC28(VCCT_GXBL1C_AC28) P1.L27(VCCT_GXBL1F_L27) P1.L28(VCCT_GXBL1F_L28) P1.R27(VCCT_GXBL1E_R27) P1.R28(VCCT_GXBL1E_R28) P1.W27(VCCT_GXBL1D_W27) P1.W28(VCCT_GXBL1D_W28)
VDD_PLL1: C248.1 C249.1 C256.1 C258.1 L6.1 R222.2 U39.11(VDDO3) U39.15(VDDO2) U39.16(VDDO1) U39.20(VDDO0)
VDD_PLL2: C159.1 C176.1 C180.1 C195.1 L5.1 R119.2 U26.11(VDDO3) U26.15(VDDO2) U26.16(VDDO1) U26.20(VDDO0)
25MHZ-1: R229.1 Y3.3(OUT)
25MHZ-2: R118.1 Y1.3(OUT)
5338_SCL1: R249.1 U39.12(SCL) U43.35(PF6)
5338_SCL2: R255.1 U26.12(SCL) U43.45(PB8)
5338_SDA1: R250.1 U39.19(SDA) U43.36(PF7)
5338_SDA2: R256.1 U26.19(SDA) U43.46(PB9)
A1_1: R383.1 R384.2 U19.27(TEST/A1)
A1_2: R440.1 R441.2 U29.27(TEST/A1)
A1_3: R464.1 R465.2 U37.27(TEST/A1)
A1_4: R477.1 R478.2 U48.27(TEST/A1)
A_SPI_CLK: R216.1 U38.6(DCLK) U43.15(PA5)
A_SPI_CS: R224.1 U38.1(NCS) U43.14(PA4)
A_SPI_DI: U38.5(ASDI) U43.17(PA7)
A_SPI_DO: U38.2(DATA) U43.16(PA6)
AD1: P1.AH17(IO_2A_19_AH17/PLL_2A_CLKOUT0N/D) R408.2 R409.2
AD2: P1.AG17(IO_2A_18_AG17/PLL_2A_CLKOUT0P,P) R416.2 R417.2
ARM_GPIO0: R696.2 U43.40(PB4)
ARM_GPIO1: R698.2 U43.41(PB5)
ARM_GPIO2: R697.2 U43.42(PB6)
ARM_NRST: C611.1 J11.1 R474.2 U43.7(NRST)
ARM_PWS0: R708.1 U43.20(PB2)
ARM_PWS1: R709.1 U43.19(PB1)
ARM_PWS2: R710.1 U43.18(PB0)
ARM_SPI_CLK: R693.2 U43.26(PB13)
ARM_SPI_DI: R694.2 U43.28(PB15)
ARM_SPI_DO: R695.2 U43.27(PB14)
ARM_SPI_NSS: R691.2 U43.25(PB12)
AS_DATA0: P1.AJ11(AS_DATA0,ASDO) R703.2
AS_DATA1: P1.AK12(AS_DATA1) R704.2
AS_DATA2: P1.AK11(AS_DATA2) R705.2
AS_DATA3: P1.AF15(AS_DATA3) R706.2
CLK_USR: R154.1 U26.22(CLK0A)
CLKUSR: C196.2 P1.AK16(IO_2A_13_AK16/CLKUSR/LVDS2A_18N) R154.2
CONF_DONE: P1.AM12(CONF_DONE) R401.1
CONN_RCK+: C174.1 U26.14(CLK2A)
CONN_RCK-: C172.1 U26.13(CLK2B)
CONN_TX+0: JT1.C3(D-C3) P1.C34(GXBL1F_TX_CH1P_1F_C34)
CONN_TX+1: JT1.C4(D-C4) P1.E34(GXBL1F_TX_CH0P_1F_E34)
CONN_TX+2: JT1.C5(D-C5) P1.G34(GXBL1E_TX_CH5P_1E_G34)
CONN_TX+3: JT1.C6(D-C6) P1.J34(GXBL1E_TX_CH4P_1E_J34)
CONN_TX+4: JT1.C7(D-C7) P1.L34(GXBL1E_TX_CH3P_1E_L34)
CONN_TX+5: JT1.C8(D-C8) P1.N34(GXBL1E_TX_CH2P_1E_N34)
CONN_TX+6: JT1.C9(D-C9) P1.R34(GXBL1E_TX_CH1P_1E_R34)
CONN_TX+7: JT1.C10(D-C10) P1.U34(GXBL1E_TX_CH0P_1E_U34)
CONN_TX-0: JT1.D3(D-D3) P1.C33(GXBL1F_TX_CH1N_1F_C33)
CONN_TX-1: JT1.D4(D-D4) P1.E33(GXBL1F_TX_CH0N_1F_E33)
CONN_TX-2: JT1.D5(D-D5) P1.G33(GXBL1E_TX_CH5N_1E_G33)
CONN_TX-3: JT1.D6(D-D6) P1.J33(GXBL1E_TX_CH4N_1E_J33)
CONN_TX-4: JT1.D7(D-D7) P1.L33(GXBL1E_TX_CH3N_1E_L33)
CONN_TX-5: JT1.D8(D-D8) P1.N33(GXBL1E_TX_CH2N_1E_N33)
CONN_TX-6: JT1.D9(D-D9) P1.R33(GXBL1E_TX_CH1N_1E_R33)
CONN_TX-7: JT1.D10(D-D10) P1.U33(GXBL1E_TX_CH0N_1E_U33)
CONN_TX_RCK+: C174.2 P1.V28(REFCLK_GXBL1E_CHBP_1E_V28)
CONN_TX_RCK-: C172.2 P1.V27(REFCLK_GXBL1E_CHBN_1E_V27)
DCLK: P1.AJ10(DCLK) R42.1
DCLK1: R41.1 R42.2 U6.B2(C)
DDR3_A_A0: P1.H27(IO_2K_12_H27/LVDS2K_18P/DQ13) R35.2 U10.N3(A0) U11.N3(A0) U12.N3(A0)
DDR3_A_A1: P1.G27(IO_2K_13_G27/LVDS2K_18N/DQ13) R32.2 U10.P7(A1) U11.P7(A1) U12.P7(A1)
DDR3_A_A2: P1.G23(IO_2K_14_G23/LVDS2K_17P/DQ13) R36.2 U10.P3(A2) U11.P3(A2) U12.P3(A2)
DDR3_A_A3: P1.G22(IO_2K_15_G22/LVDS2K_17N/DQ13) R358.2 U10.N2(A3) U11.N2(A3) U12.N2(A3)
DDR3_A_A4: P1.H25(IO_2K_16_H25/LVDS2K_16P/DQS13) R365.2 U10.P8(A4) U11.P8(A4) U12.P8(A4)
DDR3_A_A5: P1.G25(IO_2K_17_G25/LVDS2K_16N/DQSN13) R357.2 U10.P2(A5) U11.P2(A5) U12.P2(A5)
DDR3_A_A6: P1.H24(IO_2K_18_H24/PLL_2K_CLKOUT0P,PL) R366.2 U10.R8(A6) U11.R8(A6) U12.R8(A6)
DDR3_A_A7: P1.H23(IO_2K_19_H23/PLL_2K_CLKOUT0N/LV) R356.2 U10.R2(A7) U11.R2(A7) U12.R2(A7)
DDR3_A_A8: P1.H22(IO_2K_20_H22/LVDS2K_14P/DQS12) R30.2 U10.T8(A8) U11.T8(A8) U12.T8(A8)
DDR3_A_A9: P1.J22(IO_2K_21_J22/LVDS2K_14N/DQSN12) R37.2 U10.R3(A9) U11.R3(A9) U12.R3(A9)
DDR3_A_A10: P1.G26(IO_2K_22_G26/CLK_2K_0P/LVDS2K_1) R363.2 U10.L7(A10/AP) U11.L7(A10/AP) U12.L7(A10/AP)
DDR3_A_A11: P1.F26(IO_2K_23_F26/CLK_2K_0N/LVDS2K_1) R31.2 U10.R7(A11) U11.R7(A11) U12.R7(A11)
DDR3_A_A12: P1.F24(IO_2K_27_F24/LVDS2K_11N/DQ11) R33.2 U10.N7(A12/BC#) U11.N7(A12/BC#) U12.N7(A12/BC#)
DDR3_A_BA0: P1.D26(IO_2K_33_D26/LVDS2K_8N/DQSN10) R359.2 U10.M2(BA0) U11.M2(BA0) U12.M2(BA0)
DDR3_A_BA1: P1.D25(IO_2K_34_D25/LVDS2K_7P/DQ10) R364.2 U10.N8(BA1) U11.N8(BA1) U12.N8(BA1)
DDR3_A_BA2: P1.C25(IO_2K_35_C25/LVDS2K_7N/DQ10) R34.2 U10.M3(BA2) U11.M3(BA2) U12.M3(BA2)
DDR3_A_CAS_N_0: P1.E26(IO_2K_32_E26/LVDS2K_8P/DQS10) R355.2 U10.K3(CAS#) U11.K3(CAS#) U12.K3(CAS#)
DDR3_A_CK_0: P1.L23(IO_2K_8_L23/LVDS2K_20P/DQS14) R380.2 U10.J7(CK) U11.J7(CK) U12.J7(CK)
DDR3_A_CK_N_0: P1.M23(IO_2K_9_M23/LVDS2K_20N/DQSN14) R380.1 U10.K7(CK#) U11.K7(CK#) U12.K7(CK#)
DDR3_A_CKE_0: P1.J27(IO_2K_6_J27/LVDS2K_21P/DQ14) R362.2 U10.K9(CKE) U11.K9(CKE) U12.K9(CKE)
DDR3_A_CS_N_0: P1.K24(IO_2K_2_K24/LVDS2K_23P/DQ15) R360.2 U10.L2(CS#) U11.L2(CS#) U12.L2(CS#)
DDR3_A_DM0: P1.AD25(IO_2J_47_AD25/LVDS2J_1N/DQ16) U11.E7(LDM)
DDR3_A_DM1: P1.AM27(IO_2J_35_AM27/LVDS2J_7N/DQ18) U11.D3(UDM)
DDR3_A_DM2: P1.AP24(IO_2J_23_AP24/CLK_2J_0N/LVDS2J_) U12.E7(LDM)
DDR3_A_DM3: P1.AE23(IO_2J_11_AE23/LVDS2J_19N/DQ22) U12.D3(UDM)
DDR3_A_DM4: P1.C23(IO_2K_47_C23/LVDS2K_1N/DQ8) U10.E7(LDM)
DDR3_A_DQ0: P1.AJ27(IO_2J_44_AJ27/LVDS2J_2P/DQS16) U11.E3(DQ0)
DDR3_A_DQ1: P1.AH27(IO_2J_45_AH27/LVDS2J_2N/DQSN16) U11.F7(DQ1)
DDR3_A_DQ2: P1.AJ26(IO_2J_42_AJ26/LVDS2J_3P/DQ16) U11.F2(DQ2)
DDR3_A_DQ3: P1.AD24(IO_2J_37_AD24/LVDS2J_6N/DQ17) U11.F8(DQ3)
DDR3_A_DQ4: P1.AJ25(IO_2J_38_AJ25/LVDS2J_5P/DQ17) U11.H3(DQ4)
DDR3_A_DQ5: P1.AE24(IO_2J_46_AE24/LVDS2J_1P/DQ16) U11.H8(DQ5)
DDR3_A_DQ6: P1.AH25(IO_2J_39_AH25/LVDS2J_5N/DQ17) U11.G2(DQ6)
DDR3_A_DQ7: P1.AH26(IO_2J_43_AH26/LVDS2J_3N/DQ16) U11.H7(DQ7)
DDR3_A_DQ8: P1.AN27(IO_2J_34_AN27/LVDS2J_7P/DQ18) U11.D7(DQ8)
DDR3_A_DQ9: P1.AP27(IO_2J_33_AP27/LVDS2J_8N/DQSN18) U11.C3(DQ9)
DDR3_A_DQ10: P1.AK26(IO_2J_31_AK26/LVDS2J_9N/DQ18) U11.C8(DQ10)
DDR3_A_DQ11: P1.AN25(IO_2J_27_AN25/LVDS2J_11N/DQ19) U11.C2(DQ11)
DDR3_A_DQ12: P1.AL26(IO_2J_25_AL26/CLK_2J_1N/LVDS2J_) U11.A7(DQ12)
DDR3_A_DQ13: P1.AP25(IO_2J_26_AP25/RZQ_2J/LVDS2J_11P) U11.A2(DQ13)
DDR3_A_DQ14: P1.AK27(IO_2J_30_AK27/LVDS2J_9P/DQ18) U11.B8(DQ14)
DDR3_A_DQ15: P1.AP26(IO_2J_32_AP26/LVDS2J_8P/DQS18) U11.A3(DQ15)
DDR3_A_DQ16: P1.AN23(IO_2J_15_AN23/LVDS2J_17N/DQ21) U12.E3(DQ0)
DDR3_A_DQ17: P1.AM23(IO_2J_14_AM23/LVDS2J_17P/DQ21) U12.F7(DQ1)
DDR3_A_DQ18: P1.AP20(IO_2J_13_AP20/LVDS2J_18N/DQ21) U12.F2(DQ2)
DDR3_A_DQ19: P1.AL24(IO_2J_20_AL24/LVDS2J_14P/DQS20) U12.F8(DQ3)
DDR3_A_DQ20: P1.AP21(IO_2J_18_AP21/PLL_2J_CLKOUT0P,P) U12.H3(DQ4)
DDR3_A_DQ21: P1.AL25(IO_2J_21_AL25/LVDS2J_14N/DQSN20) U12.H8(DQ5)
DDR3_A_DQ22: P1.AP22(IO_2J_19_AP22/PLL_2J_CLKOUT0N/L) U12.G2(DQ6)
DDR3_A_DQ23: P1.AN24(IO_2J_22_AN24/CLK_2J_0P/LVDS2J_) U12.H7(DQ7)
DDR3_A_DQ24: P1.AL23(IO_2J_2_AL23/LVDS2J_23P/DQ23) U12.D7(DQ8)
DDR3_A_DQ25: P1.AG23(IO_2J_9_AG23/LVDS2J_20N/DQSN22) U12.C3(DQ9)
DDR3_A_DQ26: P1.AK24(IO_2J_7_AK24/LVDS2J_21N/DQ22) U12.C8(DQ10)
DDR3_A_DQ27: P1.AK23(IO_2J_3_AK23/LVDS2J_23N/DQ23) U12.C2(DQ11)
DDR3_A_DQ28: P1.AF24(IO_2J_10_AF24/LVDS2J_19P/DQ22) U12.A7(DQ12)
DDR3_A_DQ29: P1.AF23(IO_2J_8_AF23/LVDS2J_20P/DQS22) U12.A2(DQ13)
DDR3_A_DQ30: P1.AJ24(IO_2J_6_AJ24/LVDS2J_21P/DQ22) U12.B8(DQ14)
DDR3_A_DQ31: P1.AK22(IO_2J_1_AK22/LVDS2J_24N/DQ23) U12.A3(DQ15)
DDR3_A_DQ32: P1.B27(IO_2K_43_B27/LVDS2K_3N/DQ8) U10.E3(DQ0)
DDR3_A_DQ33: P1.A24(IO_2K_37_A24/LVDS2K_6N/DQ9) U10.F7(DQ1)
DDR3_A_DQ34: P1.A26(IO_2K_45_A26/LVDS2K_2N/DQSN8) U10.F2(DQ2)
DDR3_A_DQ35: P1.B23(IO_2K_46_B23/LVDS2K_1P/DQ8) U10.F8(DQ3)
DDR3_A_DQ36: P1.C27(IO_2K_42_C27/LVDS2K_3P/DQ8) U10.H3(DQ4)
DDR3_A_DQ37: P1.A25(IO_2K_39_A25/LVDS2K_5N/DQ9) U10.H8(DQ5)
DDR3_A_DQ38: P1.B26(IO_2K_44_B26/LVDS2K_2P/DQS8) U10.G2(DQ6)
DDR3_A_DQ39: P1.B25(IO_2K_38_B25/LVDS2K_5P/DQ9) U10.H7(DQ7)
DDR3_A_DQS0N: P1.AF25(IO_2J_41_AF25/LVDS2J_4N/DQSN17) U11.G3(LDQS#)
DDR3_A_DQS0P: P1.AG25(IO_2J_40_AG25/LVDS2J_4P/DQS17) U11.F3(LDQS)
DDR3_A_DQS1N: P1.AM26(IO_2J_29_AM26/PLL_2J_CLKOUT1N/L) U11.B7(UDQS#)
DDR3_A_DQS1P: P1.AM25(IO_2J_28_AM25/PLL_2J_CLKOUT1P,P) U11.C7(UDQS)
DDR3_A_DQS2N: P1.AN22(IO_2J_17_AN22/LVDS2J_16N/DQSN21) U12.G3(LDQS#)
DDR3_A_DQS2P: P1.AM22(IO_2J_16_AM22/LVDS2J_16P/DQS21) U12.F3(LDQS)
DDR3_A_DQS3N: P1.AH24(IO_2J_5_AH24/LVDS2J_22N/DQSN23) U12.B7(UDQS#)
DDR3_A_DQS3P: P1.AH23(IO_2J_4_AH23/LVDS2J_22P/DQS23) U12.C7(UDQS)
DDR3_A_DQS4N: P1.D24(IO_2K_41_D24/LVDS2K_4N/DQSN9) U10.G3(LDQS#)
DDR3_A_DQS4P: P1.C24(IO_2K_40_C24/LVDS2K_4P/DQS9) U10.F3(LDQS)
DDR3_A_ODT_0: P1.K25(IO_2K_4_K25/LVDS2K_22P/DQS15) R354.2 U10.K1(ODT) U11.K1(ODT) U12.K1(ODT)
DDR3_A_RAS_N_0: P1.F23(IO_2K_31_F23/LVDS2K_9N/DQ10) R353.2 U10.J3(RAS#) U11.J3(RAS#) U12.J3(RAS#)
DDR3_A_RST_N_0: C32.1 P1.L24(IO_2K_1_L24/LVDS2K_24N/DQ15) U10.T2(RESET#) U11.T2(RESET#) U12.T2(RESET#)
DDR3_A_WE_N_0: P1.M24(IO_2K_0_M24/LVDS2K_24P/DQ15) R361.2 U10.L3(WE#) U11.L3(WE#) U12.L3(WE#)
DDR3_B_A0: P1.AP4(IO_3A_12_AP4/LVDS3A_18P/DQ61) R111.2 U8.N3(A0) U16.N3(A0) U22.N3(A0)
DDR3_B_A1: P1.AN4(IO_3A_13_AN4/LVDS3A_18N/DQ61) R103.2 U8.P7(A1) U16.P7(A1) U22.P7(A1)
DDR3_B_A2: P1.AM6(IO_3A_14_AM6/LVDS3A_17P/DQ61) R112.2 U8.P3(A2) U16.P3(A2) U22.P3(A2)
DDR3_B_A3: P1.AM5(IO_3A_15_AM5/LVDS3A_17N/DQ61) R411.2 U8.N2(A3) U16.N2(A3) U22.N2(A3)
DDR3_B_A4: P1.AM1(IO_3A_16_AM1/LVDS3A_16P/DQS61) R394.2 U8.P8(A4) U16.P8(A4) U22.P8(A4)
DDR3_B_A5: P1.AM2(IO_3A_17_AM2/LVDS3A_16N/DQSN61) R415.2 U8.P2(A5) U16.P2(A5) U22.P2(A5)
DDR3_B_A6: P1.AM3(IO_3A_18_AM3/PLL_3A_CLKOUT0P,PL) R390.2 U8.R8(A6) U16.R8(A6) U22.R8(A6)
DDR3_B_A7: P1.AL3(IO_3A_19_AL3/PLL_3A_CLKOUT0N/LV) R419.2 U8.R2(A7) U16.R2(A7) U22.R2(A7)
DDR3_B_A8: P1.AL6(IO_3A_20_AL6/LVDS3A_14P/DQS60) R92.2 U8.T8(A8) U16.T8(A8) U22.T8(A8)
DDR3_B_A9: P1.AK6(IO_3A_21_AK6/LVDS3A_14N/DQSN60) R113.2 U8.R3(A9) U16.R3(A9) U22.R3(A9)
DDR3_B_A10: P1.AL5(IO_3A_22_AL5/CLK_3A_0P/LVDS3A_1) R397.2 U8.L7(A10/AP) U16.L7(A10/AP) U22.L7(A10/AP)
DDR3_B_A11: P1.AL4(IO_3A_23_AL4/CLK_3A_0N/LVDS3A_1) R97.2 U8.R7(A11) U16.R7(A11) U22.R7(A11)
DDR3_B_A12: P1.AJ6(IO_3A_27_AJ6/LVDS3A_11N/DQ59) R106.2 U8.N7(A12/BC#) U16.N7(A12/BC#) U22.N7(A12/BC#)
DDR3_B_BA0: P1.AG7(IO_3A_33_AG7/LVDS3A_8N/DQSN58) R407.2 U8.M2(BA0) U16.M2(BA0) U22.M2(BA0)
DDR3_B_BA1: P1.AH8(IO_3A_34_AH8/LVDS3A_7P/DQ58) R395.2 U8.N8(BA1) U16.N8(BA1) U22.N8(BA1)
DDR3_B_BA2: P1.AG8(IO_3A_35_AG8/LVDS3A_7N/DQ58) R109.2 U8.M3(BA2) U16.M3(BA2) U22.M3(BA2)
DDR3_B_CAS_N_0: P1.AH7(IO_3A_32_AH7/LVDS3A_8P/DQS58) R424.2 U8.K3(CAS#) U16.K3(CAS#) U22.K3(CAS#)
DDR3_B_CK_0: P1.AP7(IO_3A_8_AP7/LVDS3A_20P/DQS62) R405.2 U8.J7(CK) U16.J7(CK) U22.J7(CK)
DDR3_B_CK_N_0: P1.AP6(IO_3A_9_AP6/LVDS3A_20N/DQSN62) R405.1 U8.K7(CK#) U16.K7(CK#) U22.K7(CK#)
DDR3_B_CKE_0: P1.AN8(IO_3A_6_AN8/LVDS3A_21P/DQ62) R399.2 U8.K9(CKE) U16.K9(CKE) U22.K9(CKE)
DDR3_B_CS_N_0: P1.AL9(IO_3A_2_AL9/LVDS3A_23P/DQ63) R404.2 U8.L2(CS#) U16.L2(CS#) U22.L2(CS#)
DDR3_B_DM0: P1.AB11(IO_3B_47_AB11/LVDS3B_1N/DQ48) U22.E7(LDM)
DDR3_B_DM1: P1.AC7(IO_3B_35_AC7/LVDS3B_7N/DQ50) U22.D3(UDM)
DDR3_B_DM2: P1.AE3(IO_3B_23_AE3/CLK_3B_0N/LVDS3B_1) U16.E7(LDM)
DDR3_B_DM3: P1.AG2(IO_3B_11_AG2/LVDS3B_19N/DQ54) U16.D3(UDM)
DDR3_B_DM4: P1.AE9(IO_3A_47_AE9/LVDS3A_1N/DQ56) U8.E7(LDM)
DDR3_B_DQ0: P1.AD2(IO_3B_44_AD2/LVDS3B_2P/DQS48) U22.E3(DQ0)
DDR3_B_DQ1: P1.AE4(IO_3B_42_AE4/LVDS3B_3P/DQ48) U22.F7(DQ1)
DDR3_B_DQ2: P1.AB5(IO_3B_39_AB5/LVDS3B_5N/DQ49) U22.F2(DQ2)
DDR3_B_DQ3: P1.AB10(IO_3B_46_AB10/LVDS3B_1P/DQ48) U22.F8(DQ3)
DDR3_B_DQ4: P1.AD1(IO_3B_45_AD1/LVDS3B_2N/DQSN48) U22.H3(DQ4)
DDR3_B_DQ5: P1.AD4(IO_3B_43_AD4/LVDS3B_3N/DQ48) U22.H8(DQ5)
DDR3_B_DQ6: P1.AB6(IO_3B_38_AB6/LVDS3B_5P/DQ49) U22.G2(DQ6)
DDR3_B_DQ7: P1.AC5(IO_3B_37_AC5/LVDS3B_6N/DQ49) U22.H7(DQ7)
DDR3_B_DQ8: P1.AD6(IO_3B_33_AD6/LVDS3B_8N/DQSN50) U22.D7(DQ8)
DDR3_B_DQ9: P1.AD7(IO_3B_34_AD7/LVDS3B_7P/DQ50) U22.C3(DQ9)
DDR3_B_DQ10: P1.AE6(IO_3B_26_AE6/RZQ_3B/LVDS3B_11P/) U22.C8(DQ10)
DDR3_B_DQ11: P1.AC10(IO_3B_31_AC10/LVDS3B_9N/DQ50) U22.C2(DQ11)
DDR3_B_DQ12: P1.AD5(IO_3B_32_AD5/LVDS3B_8P/DQS50) U22.A7(DQ12)
DDR3_B_DQ13: P1.AD11(IO_3B_25_AD11/CLK_3B_1N/LVDS3B_) U22.A2(DQ13)
DDR3_B_DQ14: P1.AE7(IO_3B_27_AE7/LVDS3B_11N/DQ51) U22.B8(DQ14)
DDR3_B_DQ15: P1.AC9(IO_3B_30_AC9/LVDS3B_9P/DQ50) U22.A3(DQ15)
DDR3_B_DQ16: P1.AF4(IO_3B_18_AF4/PLL_3B_CLKOUT0P,PL) U16.E3(DQ0)
DDR3_B_DQ17: P1.AG5(IO_3B_20_AG5/LVDS3B_14P/DQS52) U16.F7(DQ1)
DDR3_B_DQ18: P1.AF3(IO_3B_19_AF3/PLL_3B_CLKOUT0N/LV) U16.F2(DQ2)
DDR3_B_DQ19: P1.AF6(IO_3B_15_AF6/LVDS3B_17N/DQ53) U16.F8(DQ3)
DDR3_B_DQ20: P1.AG3(IO_3B_13_AG3/LVDS3B_18N/DQ53) U16.H3(DQ4)
DDR3_B_DQ21: P1.AG6(IO_3B_14_AG6/LVDS3B_17P/DQ53) U16.H8(DQ5)
DDR3_B_DQ22: P1.AE2(IO_3B_22_AE2/CLK_3B_0P/LVDS3B_1) U16.G2(DQ6)
DDR3_B_DQ23: P1.AF5(IO_3B_21_AF5/LVDS3B_14N/DQSN52) U16.H7(DQ7)
DDR3_B_DQ24: P1.AJ2(IO_3B_3_AJ2/LVDS3B_23N/DQ55) U16.D7(DQ8)
DDR3_B_DQ25: P1.AK1(IO_3B_1_AK1/LVDS3B_24N/DQ55) U16.C3(DQ9)
DDR3_B_DQ26: P1.AJ4(IO_3B_6_AJ4/LVDS3B_21P/DQ54) U16.C8(DQ10)
DDR3_B_DQ27: P1.AH2(IO_3B_9_AH2/LVDS3B_20N/DQSN54) U16.C2(DQ11)
DDR3_B_DQ28: P1.AK2(IO_3B_2_AK2/LVDS3B_23P/DQ55) U16.A7(DQ12)
DDR3_B_DQ29: P1.AG1(IO_3B_10_AG1/LVDS3B_19P/DQ54) U16.A2(DQ13)
DDR3_B_DQ30: P1.AH4(IO_3B_7_AH4/LVDS3B_21N/DQ54) U16.B8(DQ14)
DDR3_B_DQ31: P1.AJ1(IO_3B_8_AJ1/LVDS3B_20P/DQS54) U16.A3(DQ15)
DDR3_B_DQ32: P1.AF9(IO_3A_46_AF9/LVDS3A_1P/DQ56) U8.E3(DQ0)
DDR3_B_DQ33: P1.AG11(IO_3A_39_AG11/LVDS3A_5N/DQ57) U8.F7(DQ1)
DDR3_B_DQ34: P1.AF8(IO_3A_44_AF8/LVDS3A_2P/DQS56) U8.F2(DQ2)
DDR3_B_DQ35: P1.AF11(IO_3A_38_AF11/LVDS3A_5P/DQ57) U8.F8(DQ3)
DDR3_B_DQ36: P1.AH9(IO_3A_43_AH9/LVDS3A_3N/DQ56) U8.H3(DQ4)
DDR3_B_DQ37: P1.AE11(IO_3A_37_AE11/LVDS3A_6N/DQ57) U8.H8(DQ5)
DDR3_B_DQ38: P1.AE8(IO_3A_45_AE8/LVDS3A_2N/DQSN56) U8.G2(DQ6)
DDR3_B_DQ39: P1.AH10(IO_3A_42_AH10/LVDS3A_3P/DQ56) U8.H7(DQ7)
DDR3_B_DQS0N: P1.AB7(IO_3B_41_AB7/LVDS3B_4N/DQSN49) U22.G3(LDQS#)
DDR3_B_DQS0P: P1.AB8(IO_3B_40_AB8/LVDS3B_4P/DQS49) U22.F3(LDQS)
DDR3_B_DQS1N: P1.AD9(IO_3B_29_AD9/PLL_3B_CLKOUT1N/LV) U22.B7(UDQS#)
DDR3_B_DQS1P: P1.AC8(IO_3B_28_AC8/PLL_3B_CLKOUT1P,PL) U22.C7(UDQS)
DDR3_B_DQS2N: P1.AE1(IO_3B_17_AE1/LVDS3B_16N/DQSN53) U16.G3(LDQS#)
DDR3_B_DQS2P: P1.AF1(IO_3B_16_AF1/LVDS3B_16P/DQS53) U16.F3(LDQS)
DDR3_B_DQS3N: P1.AK3(IO_3B_5_AK3/LVDS3B_22N/DQSN55) U16.B7(UDQS#)
DDR3_B_DQS3P: P1.AK4(IO_3B_4_AK4/LVDS3B_22P/DQS55) U16.C7(UDQS)
DDR3_B_DQS4N: P1.AF10(IO_3A_41_AF10/LVDS3A_4N/DQSN57) U8.G3(LDQS#)
DDR3_B_DQS4P: P1.AG10(IO_3A_40_AG10/LVDS3A_4P/DQS57) U8.F3(LDQS)
DDR3_B_ODT_0: P1.AP9(IO_3A_4_AP9/LVDS3A_22P/DQS63) R423.2 U8.K1(ODT) U16.K1(ODT) U22.K1(ODT)
DDR3_B_RAS_N_0: P1.AK8(IO_3A_31_AK8/LVDS3A_9N/DQ58) R426.2 U8.J3(RAS#) U16.J3(RAS#) U22.J3(RAS#)
DDR3_B_RST_N_0: C147.1 P1.AM7(IO_3A_1_AM7/LVDS3A_24N/DQ63) U8.T2(RESET#) U16.T2(RESET#) U22.T2(RESET#)
DDR3_B_WE_N_0: P1.AN7(IO_3A_0_AN7/LVDS3A_24P/DQ63) R402.2 U8.L3(WE#) U16.L3(WE#) U22.L3(WE#)
DDR3_C_A0: P1.L4(IO_3D_12_L4/LVDS3D_18P/DQ37) R152.2 U28.N3(A0) U32.N3(A0) U40.N3(A0)
DDR3_C_A1: P1.K4(IO_3D_13_K4/LVDS3D_18N/DQ37) R143.2 U28.P7(A1) U32.P7(A1) U40.P7(A1)
DDR3_C_A2: P1.N4(IO_3D_14_N4/LVDS3D_17P/DQ37) R156.2 U28.P3(A2) U32.P3(A2) U40.P3(A2)
DDR3_C_A3: P1.N5(IO_3D_15_N5/LVDS3D_17N/DQ37) R456.2 U28.N2(A3) U32.N2(A3) U40.N2(A3)
DDR3_C_A4: P1.J4(IO_3D_16_J4/LVDS3D_16P/DQS37) R430.2 U28.P8(A4) U32.P8(A4) U40.P8(A4)
DDR3_C_A5: P1.J5(IO_3D_17_J5/LVDS3D_16N/DQSN37) R458.2 U28.P2(A5) U32.P2(A5) U40.P2(A5)
DDR3_C_A6: P1.M5(IO_3D_18_M5/PLL_3D_CLKOUT0P,PLL) R431.2 U28.R8(A6) U32.R8(A6) U40.R8(A6)
DDR3_C_A7: P1.L5(IO_3D_19_L5/PLL_3D_CLKOUT0N/LVD) R459.2 U28.R2(A7) U32.R2(A7) U40.R2(A7)
DDR3_C_A8: P1.M6(IO_3D_20_M6/LVDS3D_14P/DQS36) R139.2 U28.T8(A8) U32.T8(A8) U40.T8(A8)
DDR3_C_A9: P1.M7(IO_3D_21_M7/LVDS3D_14N/DQSN36) R157.2 U28.R3(A9) U32.R3(A9) U40.R3(A9)
DDR3_C_A10: P1.K6(IO_3D_22_K6/CLK_3D_0P/LVDS3D_13) R433.2 U28.L7(A10/AP) U32.L7(A10/AP) U40.L7(A10/AP)
DDR3_C_A11: P1.L6(IO_3D_23_L6/CLK_3D_0N/LVDS3D_13) R141.2 U28.R7(A11) U32.R7(A11) U40.R7(A11)
DDR3_C_A12: P1.L8(IO_3D_27_L8/LVDS3D_11N/DQ35) R145.2 U28.N7(A12/BC#) U32.N7(A12/BC#) U40.N7(A12/BC#)
DDR3_C_BA0: P1.P7(IO_3D_33_P7/LVDS3D_8N/DQSN34) R451.2 U28.M2(BA0) U32.M2(BA0) U40.M2(BA0)
DDR3_C_BA1: P1.N9(IO_3D_34_N9/LVDS3D_7P/DQ34) R432.2 U28.N8(BA1) U32.N8(BA1) U40.N8(BA1)
DDR3_C_BA2: P1.P9(IO_3D_35_P9/LVDS3D_7N/DQ34) R148.2 U28.M3(BA2) U32.M3(BA2) U40.M3(BA2)
DDR3_C_CAS_N_0: P1.N7(IO_3D_32_N7/LVDS3D_8P/DQS34) R442.2 U28.K3(CAS#) U32.K3(CAS#) U40.K3(CAS#)
DDR3_C_CK_0: P1.N2(IO_3D_8_N2/LVDS3D_20P/DQS38) R437.2 U28.J7(CK) U32.J7(CK) U40.J7(CK)
DDR3_C_CK_N_0: P1.N3(IO_3D_9_N3/LVDS3D_20N/DQSN38) R437.1 U28.K7(CK#) U32.K7(CK#) U40.K7(CK#)
DDR3_C_CKE_0: P1.L3(IO_3D_6_L3/LVDS3D_21P/DQ38) R428.2 U28.K9(CKE) U32.K9(CKE) U40.K9(CKE)
DDR3_C_CS_N_0: P1.K1(IO_3D_2_K1/LVDS3D_23P/DQ39) R449.2 U28.L2(CS#) U32.L2(CS#) U40.L2(CS#)
DDR3_C_DM0: P1.R2(IO_3C_35_R2/LVDS3C_7N/DQ42) U32.E7(LDM)
DDR3_C_DM1: P1.R4(IO_3C_47_R4/LVDS3C_1N/DQ40) U32.D3(UDM)
DDR3_C_DM2: P1.Y4(IO_3C_11_Y4/LVDS3C_19N/DQ46) U28.E7(LDM)
DDR3_C_DM3: P1.Y7(IO_3C_23_Y7/CLK_3C_0N/LVDS3C_13) U28.D3(UDM)
DDR3_C_DM4: P1.R9(IO_3D_47_R9/LVDS3D_1N/DQ32) U40.E7(LDM)
DDR3_C_DQ0: P1.P1(IO_3C_33_P1/LVDS3C_8N/DQSN42) U32.E3(DQ0)
DDR3_C_DQ1: P1.R1(IO_3C_32_R1/LVDS3C_8P/DQS42) U32.F7(DQ1)
DDR3_C_DQ2: P1.P2(IO_3C_34_P2/LVDS3C_7P/DQ42) U32.F2(DQ2)
DDR3_C_DQ3: P1.U3(IO_3C_30_U3/LVDS3C_9P/DQ42) U32.F8(DQ3)
DDR3_C_DQ4: P1.U2(IO_3C_27_U2/LVDS3C_11N/DQ43) U32.H3(DQ4)
DDR3_C_DQ5: P1.V3(IO_3C_31_V3/LVDS3C_9N/DQ42) U32.H8(DQ5)
DDR3_C_DQ6: P1.W2(IO_3C_25_W2/CLK_3C_1N/LVDS3C_12) U32.G2(DQ6)
DDR3_C_DQ7: P1.V2(IO_3C_26_V2/RZQ_3C/LVDS3C_11P/D) U32.H7(DQ7)
DDR3_C_DQ8: P1.V4(IO_3C_37_V4/LVDS3C_6N/DQ41) U32.D7(DQ8)
DDR3_C_DQ9: P1.U5(IO_3C_39_U5/LVDS3C_5N/DQ41) U32.C3(DQ9)
DDR3_C_DQ10: P1.T3(IO_3C_42_T3/LVDS3C_3P/DQ40) U32.C8(DQ10)
DDR3_C_DQ11: P1.P4(IO_3C_44_P4/LVDS3C_2P/DQS40) U32.C2(DQ11)
DDR3_C_DQ12: P1.T4(IO_3C_46_T4/LVDS3C_1P/DQ40) U32.A7(DQ12)
DDR3_C_DQ13: P1.U6(IO_3C_38_U6/LVDS3C_5P/DQ41) U32.A2(DQ13)
DDR3_C_DQ14: P1.R3(IO_3C_43_R3/LVDS3C_3N/DQ40) U32.B8(DQ14)
DDR3_C_DQ15: P1.P5(IO_3C_45_P5/LVDS3C_2N/DQSN40) U32.A3(DQ15)
DDR3_C_DQ16: P1.Y3(IO_3C_10_Y3/LVDS3C_19P/DQ46) U28.E3(DQ0)
DDR3_C_DQ17: P1.AA3(IO_3C_8_AA3/LVDS3C_20P/DQS46) U28.F7(DQ1)
DDR3_C_DQ18: P1.Y2(IO_3C_3_Y2/LVDS3C_23N/DQ47) U28.F2(DQ2)
DDR3_C_DQ19: P1.AB2(IO_3C_6_AB2/LVDS3C_21P/DQ46) U28.F8(DQ3)
DDR3_C_DQ20: P1.Y1(IO_3C_2_Y1/LVDS3C_23P/DQ47) U28.H3(DQ4)
DDR3_C_DQ21: P1.AA4(IO_3C_9_AA4/LVDS3C_20N/DQSN46) U28.H8(DQ5)
DDR3_C_DQ22: P1.AA1(IO_3C_1_AA1/LVDS3C_24N/DQ47) U28.G2(DQ6)
DDR3_C_DQ23: P1.AB3(IO_3C_7_AB3/LVDS3C_21N/DQ46) U28.H7(DQ7)
DDR3_C_DQ24: P1.AA6(IO_3C_13_AA6/LVDS3C_18N/DQ45) U28.D7(DQ8)
DDR3_C_DQ25: P1.AA8(IO_3C_14_AA8/LVDS3C_17P/DQ45) U28.C3(DQ9)
DDR3_C_DQ26: P1.W4(IO_3C_18_W4/PLL_3C_CLKOUT0P,PLL) U28.C8(DQ10)
DDR3_C_DQ27: P1.Y9(IO_3C_21_Y9/LVDS3C_14N/DQSN44) U28.C2(DQ11)
DDR3_C_DQ28: P1.W5(IO_3C_19_W5/PLL_3C_CLKOUT0N/LVD) U28.A7(DQ12)
DDR3_C_DQ29: P1.AA9(IO_3C_15_AA9/LVDS3C_17N/DQ45) U28.A2(DQ13)
DDR3_C_DQ30: P1.Y6(IO_3C_22_Y6/CLK_3C_0P/LVDS3C_13) U28.B8(DQ14)
DDR3_C_DQ31: P1.Y8(IO_3C_20_Y8/LVDS3C_14P/DQS44) U28.A3(DQ15)
DDR3_C_DQ32: P1.T9(IO_3D_46_T9/LVDS3D_1P/DQ32) U40.E3(DQ0)
DDR3_C_DQ33: P1.V8(IO_3D_39_V8/LVDS3D_5N/DQ33) U40.F7(DQ1)
DDR3_C_DQ34: P1.W9(IO_3D_37_W9/LVDS3D_6N/DQ33) U40.F2(DQ2)
DDR3_C_DQ35: P1.T8(IO_3D_45_T8/LVDS3D_2N/DQSN32) U40.F8(DQ3)
DDR3_C_DQ36: P1.U8(IO_3D_44_U8/LVDS3D_2P/DQS32) U40.H3(DQ4)
DDR3_C_DQ37: P1.V7(IO_3D_42_V7/LVDS3D_3P/DQ32) U40.H8(DQ5)
DDR3_C_DQ38: P1.V9(IO_3D_38_V9/LVDS3D_5P/DQ33) U40.G2(DQ6)
DDR3_C_DQ39: P1.U7(IO_3D_43_U7/LVDS3D_3N/DQ32) U40.H7(DQ7)
DDR3_C_DQS0N: P1.T1(IO_3C_29_T1/PLL_3C_CLKOUT1N/LVD) U32.G3(LDQS#)
DDR3_C_DQS0P: P1.U1(IO_3C_28_U1/PLL_3C_CLKOUT1P,PLL) U32.F3(LDQS)
DDR3_C_DQS1N: P1.T6(IO_3C_41_T6/LVDS3C_4N/DQSN41) U32.B7(UDQS#)
DDR3_C_DQS1P: P1.T5(IO_3C_40_T5/LVDS3C_4P/DQS41) U32.C7(UDQS)
DDR3_C_DQS2N: P1.AC2(IO_3C_5_AC2/LVDS3C_22N/DQSN47) U28.G3(LDQS#)
DDR3_C_DQS2P: P1.AC3(IO_3C_4_AC3/LVDS3C_22P/DQS47) U28.F3(LDQS)
DDR3_C_DQS3N: P1.W7(IO_3C_17_W7/LVDS3C_16N/DQSN45) U28.B7(UDQS#)
DDR3_C_DQS3P: P1.W6(IO_3C_16_W6/LVDS3C_16P/DQS45) U28.C7(UDQS)
DDR3_C_DQS4N: P1.T10(IO_3D_41_T10/LVDS3D_4N/DQSN33) U40.G3(LDQS#)
DDR3_C_DQS4P: P1.U10(IO_3D_40_U10/LVDS3D_4P/DQS33) U40.F3(LDQS)
DDR3_C_ODT_0: P1.J1(IO_3D_4_J1/LVDS3D_22P/DQS39) R438.2 U28.K1(ODT) U32.K1(ODT) U40.K1(ODT)
DDR3_C_RAS_N_0: P1.R7(IO_3D_31_R7/LVDS3D_9N/DQ34) R435.2 U28.J3(RAS#) U32.J3(RAS#) U40.J3(RAS#)
DDR3_C_RST_N_0: C198.1 P1.L1(IO_3D_1_L1/LVDS3D_24N/DQ39) U28.T2(RESET#) U32.T2(RESET#) U40.T2(RESET#)
DDR3_C_WE_N_0: P1.M1(IO_3D_0_M1/LVDS3D_24P/DQ39) R445.2 U28.L3(WE#) U32.L3(WE#) U40.L3(WE#)
DDR3A_N: C247.2 P1.E24(IO_2K_25_E24/CLK_2K_1N/LVDS2K_1)
DDR3A_P: C246.2 P1.E23(IO_2K_24_E23/CLK_2K_1P/LVDS2K_1)
DDR3B_N: C262.2 P1.AK9(IO_3A_25_AK9/CLK_3A_1N/LVDS3A_1)
DDR3B_P: C259.2 P1.AJ9(IO_3A_24_AJ9/CLK_3A_1P/LVDS3A_1)
DDR3C_N: C251.2 P1.P6(IO_3D_25_P6/CLK_3D_1N/LVDS3D_12)
DDR3C_P: C250.2 P1.R6(IO_3D_24_R6/CLK_3D_1P/LVDS3D_12)
DEM_D0: R341.1 R342.1 U59.53(DEM_D0)
DEM_D1: R338.1 R339.1 U59.54(DEM_D1)
ENSMB: R350.1 R351.1 U59.48(ENSMB)
EQ_D0: R337.1 R340.1 U59.20(EQ_D0)
EQ_D1: R335.1 R336.1 U59.19(EQ_D1)
EQ_S0: R371.1 R372.1 U59.46(EQ_S0)
EQ_S1: R368.1 R369.1 U59.47(EQ_S1)
EQ_SEL/A0_1: R66.2 R67.1 U19.21(EQ_SEL/A0)
EQ_SEL/A0_2: R123.2 R124.1 U29.21(EQ_SEL/A0)
EQ_SEL/A0_3: R200.2 R201.1 U37.21(EQ_SEL/A0)
EQ_SEL/A0_4: R262.2 R263.1 U48.21(EQ_SEL/A0)
F_ARM_GPIO0: P1.E19(IO_2L_31_E19/DQ2) R696.1
F_ARM_GPIO1: P1.D19(IO_2L_47_D19/DQ0) R698.1
F_ARM_GPIO2: P1.F19(IO_2L_30_F19/DQ2) R697.1
F_ARM_SPI_CLK: P1.F18(IO_2L_20_F18/DQS4) R693.1
F_ARM_SPI_DI: P1.H19(IO_2L_23_H19/CLK_2L_0N/DQ4) R694.1
F_ARM_SPI_DO: P1.E18(IO_2L_25_E18/CLK_2L_1N/DQ3) R695.1
F_ARM_SPI_NSS: P1.G18(IO_2L_18_G18/PLL_2L_CLKOUT0P,PL) R691.1
F_HM21_SCL: P1.L18(IO_2L_3_L18/DQ7) R187.1
F_HM21_SDA: P1.K18(IO_2L_2_K18/DQ7) R186.1
F_HM_TX_SCL1: P1.B21(IO_2L_44_B21/DQS0) R183.1
F_HM_TX_SCL2: P1.D20(IO_2L_35_D20/DQ2) R185.1
F_HM_TX_SCL3: P1.F20(IO_2L_27_F20/DQ3) R180.1
F_HM_TX_SCL4: P1.L20(IO_2L_10_L20/DQ6) R189.1
F_HM_TX_SCL21: P1.M18(IO_2L_1_M18/DQ7) R190.1
F_HM_TX_SDA1: P1.A21(IO_2L_43_A21/DQ0) R182.1
F_HM_TX_SDA2: P1.C20(IO_2L_34_C20/DQ2) R184.1
F_HM_TX_SDA3: P1.G20(IO_2L_26_G20/RZQ_2L/DQ3) R179.1
F_HM_TX_SDA4: P1.L19(IO_2L_9_L19/DQSN6) R188.1
F_HM_TX_SDA21: P1.M17(IO_2L_0_M17/DQ7) R191.1
F_NCS0: P1.AN10(NCSO0) R707.1
F_RX_5V_N: P1.K21(IO_2L_6_K21/DQ6) R192.1
F_RX_HPD_N: P1.L21(IO_2L_5_L21/DQSN7) R181.1
FCLT_GPIO0: P1.E17(IO_2L_24_E17/CLK_2L_1P/DQ3) R711.1
FCLT_GPIO1: P1.H18(IO_2L_19_H18/PLL_2L_CLKOUT0N/DQ) R712.1
FCLT_GPIO2: P1.G21(IO_2L_16_G21/DQS5) R713.1
FCLT_GPIO3: P1.G17(IO_2L_21_G17/DQSN4) R714.1
FCLT_GPIO4: P1.H17(IO_2L_15_H17/DQ5) R51.1
FCLT_GPIO5: P1.J17(IO_2L_14_J17/DQ5) R47.1
FCLT_GPIO6: P1.D22(IO_2L_32_D22/DQS2) R54.1
FCLT_GPIO7: P1.M21(IO_2L_4_M21/DQS7) R53.1
HD_SCL1: R98.2 R104.1 R107.2 U21.6(SCL2)
HD_SCL2: R165.2 R171.1 R173.2 U31.6(SCL2)
HD_SCL3: R234.2 R241.1 R243.2 U42.6(SCL2)
HD_SCL4: R294.2 R299.1 R301.2 U55.6(SCL2)
HD_SDA1: R99.2 R100.1 R108.2 U21.5(SDA2)
HD_SDA2: R166.2 R167.1 R174.2 U31.5(SDA2)
HD_SDA3: R235.2 R236.1 R244.2 U42.5(SDA2)
HD_SDA4: R295.2 R296.1 R302.2 U55.5(SDA2)
HDMI20_RX_RCK+: C428.1 U59.31(S_OUTA1P)
HDMI20_RX_RCK-: C426.1 U59.30(S_OUTA1N)
HDMI21_RX+: C264.1 U39.22(CLK0A)
HDMI21_RX-: C261.1 U39.21(CLK0B)
HDMI21_RX_RCK+: C264.2 P1.AF28(REFCLK_GXBL1C_CHBP_1C_AF28)
HDMI21_RX_RCK-: C261.2 P1.AF27(REFCLK_GXBL1C_CHBN_1C_AF27)
HDMI_1_TCX+: J6.10(CLK+) R82.2 U17.4(IO3) U17.7(NC3) U19.26(OUT_CLKP)
HDMI_1_TCX-: J6.12(CLK-) R80.2 U17.5(IO4) U17.6(NC4) U19.25(OUT_CLKN)
HDMI_1_TX0+: J6.7(DAT0+) R84.2 U17.1(IO1) U17.10(NC1) U19.29(OUT_D0P)
HDMI_1_TX0-: J6.9(DAT0-) R83.2 U17.2(IO2) U17.9(NC2) U19.28(OUT_D0N)
HDMI_1_TX1+: J6.4(DAT1+) R86.2 U19.32(OUT_D1P) U20.4(IO3) U20.7(NC3)
HDMI_1_TX1-: J6.6(DAT1-) R85.2 U19.31(OUT_D1N) U20.5(IO4) U20.6(NC4)
HDMI_1_TX2+: J6.1(DAT2+) R88.2 U19.35(OUT_D2P) U20.1(IO1) U20.10(NC1)
HDMI_1_TX2-: J6.3(DAT2-) R87.2 U19.34(OUT_D2N) U20.2(IO2) U20.9(NC2)
HDMI_2_TCX+: J8.10(CLK+) R144.2 U27.4(IO3) U27.7(NC3) U29.26(OUT_CLKP)
HDMI_2_TCX-: J8.12(CLK-) R142.2 U27.5(IO4) U27.6(NC4) U29.25(OUT_CLKN)
HDMI_2_TX0+: J8.7(DAT0+) R149.2 U27.1(IO1) U27.10(NC1) U29.29(OUT_D0P)
HDMI_2_TX0-: J8.9(DAT0-) R146.2 U27.2(IO2) U27.9(NC2) U29.28(OUT_D0N)
HDMI_2_TX1+: J8.4(DAT1+) R153.2 U29.32(OUT_D1P) U30.4(IO3) U30.7(NC3)
HDMI_2_TX1-: J8.6(DAT1-) R150.2 U29.31(OUT_D1N) U30.5(IO4) U30.6(NC4)
HDMI_2_TX2+: J8.1(DAT2+) R158.2 U29.35(OUT_D2P) U30.1(IO1) U30.10(NC1)
HDMI_2_TX2-: J8.3(DAT2-) R155.2 U29.34(OUT_D2N) U30.2(IO2) U30.9(NC2)
HDMI_3_TCX+: J10.10(CLK+) R214.2 U36.4(IO3) U36.7(NC3) U37.26(OUT_CLKP)
HDMI_3_TCX-: J10.12(CLK-) R213.2 U36.5(IO4) U36.6(NC4) U37.25(OUT_CLKN)
HDMI_3_TX0+: J10.7(DAT0+) R217.2 U36.1(IO1) U36.10(NC1) U37.29(OUT_D0P)
HDMI_3_TX0-: J10.9(DAT0-) R215.2 U36.2(IO2) U36.9(NC2) U37.28(OUT_D0N)
HDMI_3_TX1+: J10.4(DAT1+) R219.2 U37.32(OUT_D1P) U41.4(IO3) U41.7(NC3)
HDMI_3_TX1-: J10.6(DAT1-) R218.2 U37.31(OUT_D1N) U41.5(IO4) U41.6(NC4)
HDMI_3_TX2+: J10.1(DAT2+) R223.2 U37.35(OUT_D2P) U41.1(IO1) U41.10(NC1)
HDMI_3_TX2-: J10.3(DAT2-) R220.2 U37.34(OUT_D2N) U41.2(IO2) U41.9(NC2)
HDMI_4_TCX+: J14.10(CLK+) R276.2 U47.4(IO3) U47.7(NC3) U48.26(OUT_CLKP)
HDMI_4_TCX-: J14.12(CLK-) R275.2 U47.5(IO4) U47.6(NC4) U48.25(OUT_CLKN)
HDMI_4_TX0+: J14.7(DAT0+) R278.2 U47.1(IO1) U47.10(NC1) U48.29(OUT_D0P)
HDMI_4_TX0-: J14.9(DAT0-) R277.2 U47.2(IO2) U47.9(NC2) U48.28(OUT_D0N)
HDMI_4_TX1+: J14.4(DAT1+) R280.2 U48.32(OUT_D1P) U49.4(IO3) U49.7(NC3)
HDMI_4_TX1-: J14.6(DAT1-) R279.2 U48.31(OUT_D1N) U49.5(IO4) U49.6(NC4)
HDMI_4_TX2+: J14.1(DAT2+) R282.2 U48.35(OUT_D2P) U49.1(IO1) U49.10(NC1)
HDMI_4_TX2-: J14.3(DAT2-) R281.2 U48.34(OUT_D2N) U49.2(IO2) U49.9(NC2)
HDMI_HPD_21: HDMI1.19(HPLG) Q2.3(D) R8.2 U3.4(IO3) U3.7(NC3)
HDMI_HPD_IN1: Q3.3(D) R77.2 R385.2 R386.2
HDMI_HPD_IN2: Q4.3(D) R137.2 R444.2 R446.2
HDMI_HPD_IN3: Q5.3(D) R210.2 R466.2 R467.2
HDMI_HPD_IN4: Q6.3(D) R273.2 R479.2 R480.2
HDMI_RX0N: C398.1 HDMI1.3(DAT2-) R25.2 U7.2(IO2) U7.9(NC2)
HDMI_RX0P: C399.1 HDMI1.1(DAT2+) R39.2 U7.1(IO1) U7.10(NC1)
